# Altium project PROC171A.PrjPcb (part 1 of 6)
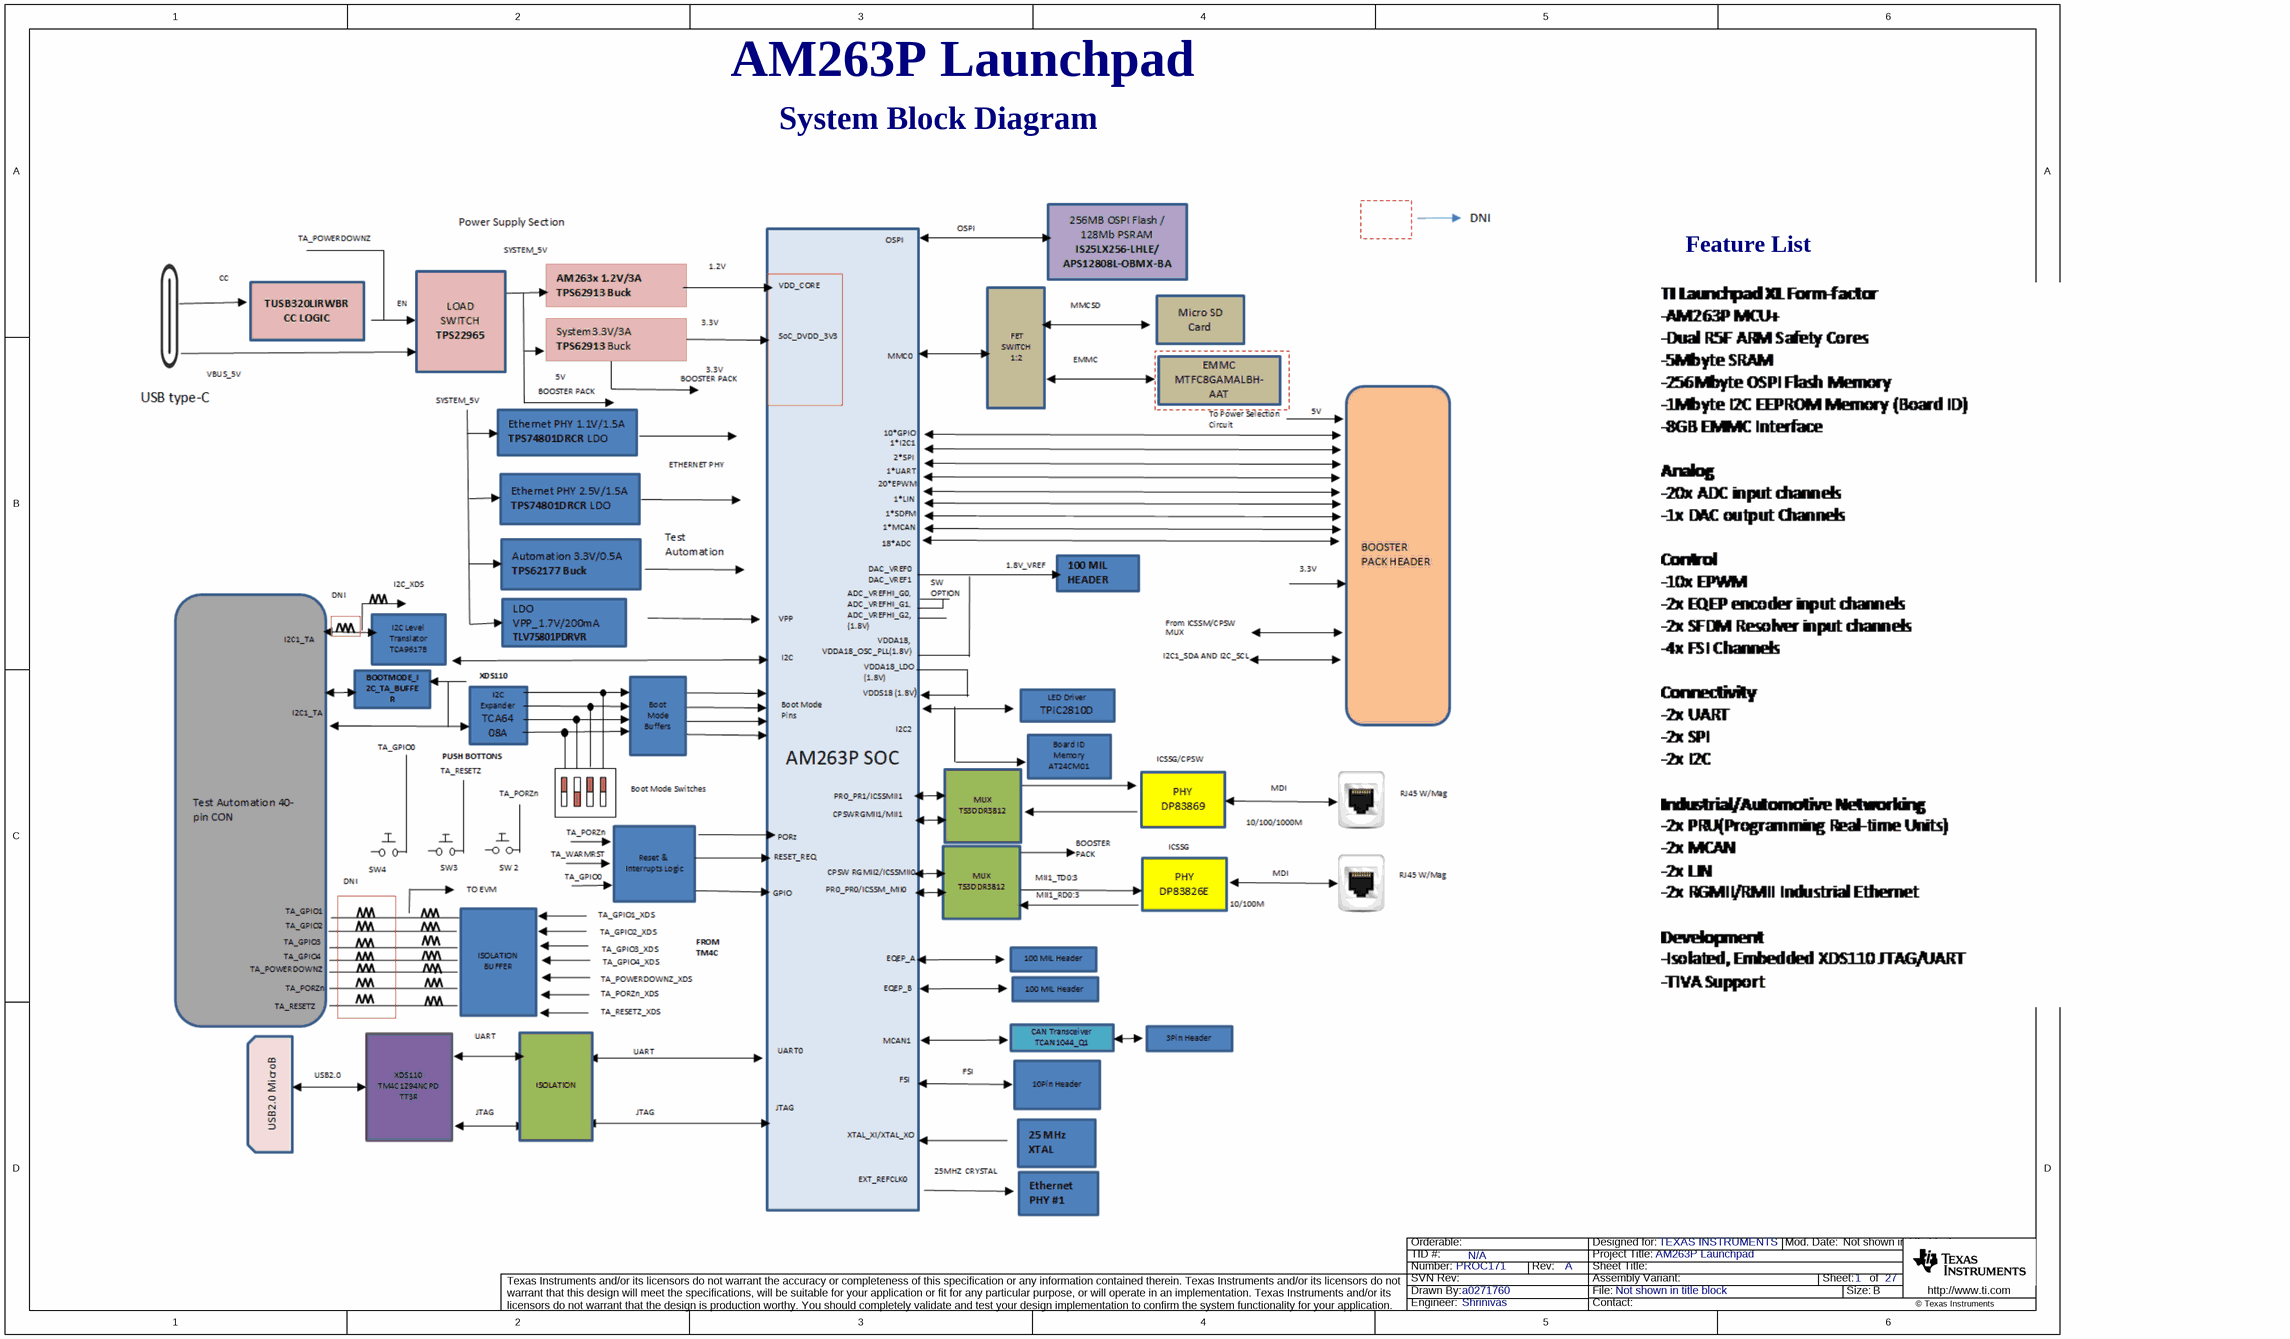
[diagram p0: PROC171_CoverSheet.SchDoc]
DrawnBy: a0271760; Layout Engineer: MISTRAL; PCB_Rev: A; PRJ_Customer: TEXAS INSTRUMENTS; PRJ_Engineer: Shrinivas; PRJ_Number: PROC171; PRJ_Title: AM263P Launchpad; Sch_Rev: A; TID: N/A
27 sheets, 919 parts. Net scope: global (net labels, ports and power ports of the same name join across sheets).
Sheets:
  PROC171_CoverSheet.SchDoc
  PROC171_Revision_History.SchDoc
  PROC171_System_Power_1.SchDoc
  PROC171_System_Power_2.SchDoc
  PROC171_AM263P_1_Power.SchDoc
  PROC171_AM263P_2_Clock_Reset_Boot_JTAG.SchDoc
  PROC171_AM263P_Serial_Connectivity.SchDoc
  PROC171_AM263P_3_OSPI_MMC.SchDoc
  PROC171_AM263P_4_EMMC.SchDoc
  PROC171_AM263P_5_ADC_DAC.SchDoc
  PROC171_AM263P_6_ePWM_eQEP_FSI.SchDoc
  PROC171_AM263P_7_RGMII_MII.SchDoc
  PROC171_AM263P_8_PRU.SchDoc
  PROC171_AM263P_9_SDFM.SchDoc
  PROC171_Push_Buttons.SchDoc
  PROC171_Test_Automation.SchDoc
  PROC171_Ehernet_PHY_1.SchDoc
  PROC171_Ehernet_PHY_2.SchDoc
  PROC171_Ehernet_RJ45_1.SchDoc
  PROC171_XDS110_2.SchDoc
  PROC171_Ehernet_RJ45_2.SchDoc
  PROC171_Boosterpack_Headers.SchDoc
  PROC171_Breakout_Headers.SchDoc
  PROC171_IO_EXPANDER.SchDoc
  PROC171_LED.SchDoc
  PROC171_XDS110_1.SchDoc
  PROC171_Hardware.SchDoc

## Sheet PROC171_CoverSheet.SchDoc
size 431 x 279 mm; Date: Not shown in title block; ApprovedBy: Not shown in title block; CheckedBy: Not shown in title block; Author: Not shown in title block; CompanyName: Not shown in title block; Engineer: Shrinivas/Rakesh; Organization: Not shown in title block; Address1: Not shown in title block; Address2: Not shown in title block; Address3: Not shown in title block; Address4: Not shown in title block; DocumentNumber: 1; Rev: A; SheetNumber: 1; SheetTotal: 27; PageSetup: Record=PageOptions¦CenterHorizontal=True¦CenterVertical=True¦PrintScale=1.00¦XCorrection=1.00¦YCorrection=1.00¦PrintKind=0¦BorderSize=5000000¦LeftOffset=0¦BottomOffset=0¦Orientation=2¦PaperLength=1000¦PaperWidth=1000¦Scale=100¦PaperSource=15¦PrintQuality=600¦MediaType=1¦DitherType=10¦PaperKind=Letter¦PrintScaleMode=1; Revision: E1

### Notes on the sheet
- AM263P Launchpad
- System Block Diagram
- Feature List

## Sheet PROC171_Revision_History.SchDoc
size 431 x 279 mm; Date: Not shown in title block; ApprovedBy: Not shown in title block; CheckedBy: Not shown in title block; Author: Not shown in title block; CompanyName: Not shown in title block; Engineer: Shrinivas/Rakesh; Organization: Not shown in title block; Address1: Not shown in title block; Address2: Not shown in title block; Address3: Not shown in title block; Address4: Not shown in title block; DocumentNumber: 2; Rev: A; SheetNumber: 2; SheetTotal: 27; PageSetup: Record=PageOptions¦CenterHorizontal=True¦CenterVertical=True¦PrintScale=1.00¦XCorrection=1.00¦YCorrection=1.00¦PrintKind=0¦BorderSize=5000000¦LeftOffset=0¦BottomOffset=0¦Orientation=2¦PaperLength=1000¦PaperWidth=1000¦Scale=100¦PaperSource=15¦PrintQuality=600¦MediaType=1¦DitherType=10¦PaperKind=Letter¦PrintScaleMode=1; Revision: E1
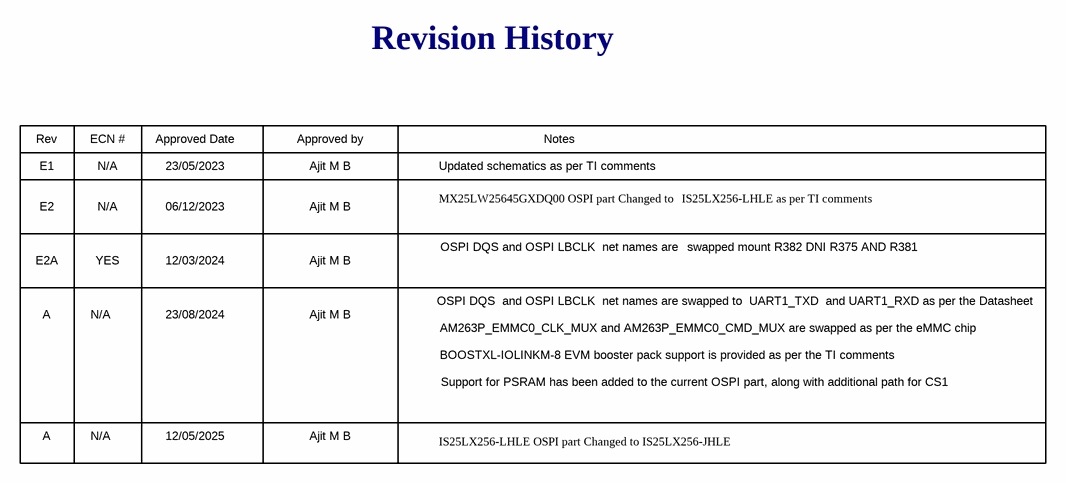
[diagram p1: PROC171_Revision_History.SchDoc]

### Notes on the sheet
- Revision History
- Rev
- ECN #
- Approved Date
- Approved by
- Notes
- E1
- E2
- N/A
- 23/05/2023
- 06/12/2023
- Ajit M B
- Updated schematics as per TI comments
- MX25LW25645GXDQ00 OSPI part Changed to
- IS25LX256-LHLE as per TI comments
- E2A
- YES
- 12/03/2024
- OSPI DQS and OSPI LBCLK  net names are
- swapped mount R382 DNI R375 AND R381
- A
- 23/08/2024
- BOOSTXL-IOLINKM-8 EVM booster pack support is provided as per the TI comments
- AM263P_EMMC0_CLK_MUX and AM263P_EMMC0_CMD_MUX are swapped as per the eMMC chip
- OSPI DQS  and OSPI LBCLK  net names are swapped to  UART1_TXD  and UART1_RXD as per the Datasheet
- Support for PSRAM has been added to the current OSPI part, along with additional path for CS1
- 12/05/2025
- IS25LX256-LHLE OSPI part Changed to IS25LX256-JHLE

## Sheet PROC171_System_Power_1.SchDoc
size 431 x 279 mm; Date: Not shown in title block; ApprovedBy: Not shown in title block; CheckedBy: Not shown in title block; Author: Not shown in title block; CompanyName: Not shown in title block; Engineer: Not shown in title block; Organization: Not shown in title block; Address1: Not shown in title block; Address2: Not shown in title block; Address3: Not shown in title block; Address4: Not shown in title block; DocumentNumber: 3; Revision: Use project parameter SCH_Rev; SheetNumber: 3; SheetTotal: 27; PageSetup: Record=PageOptions¦CenterHorizontal=True¦CenterVertical=True¦PrintScale=1.00¦XCorrection=1.00¦YCorrection=1.00¦PrintKind=0¦BorderSize=5000000¦LeftOffset=0¦BottomOffset=0¦Orientation=2¦PaperLength=1000¦PaperWidth=1000¦Scale=100¦PaperSource=15¦PrintQuality=600¦MediaType=1¦DitherType=10¦PaperKind=Letter¦PrintScaleMode=1
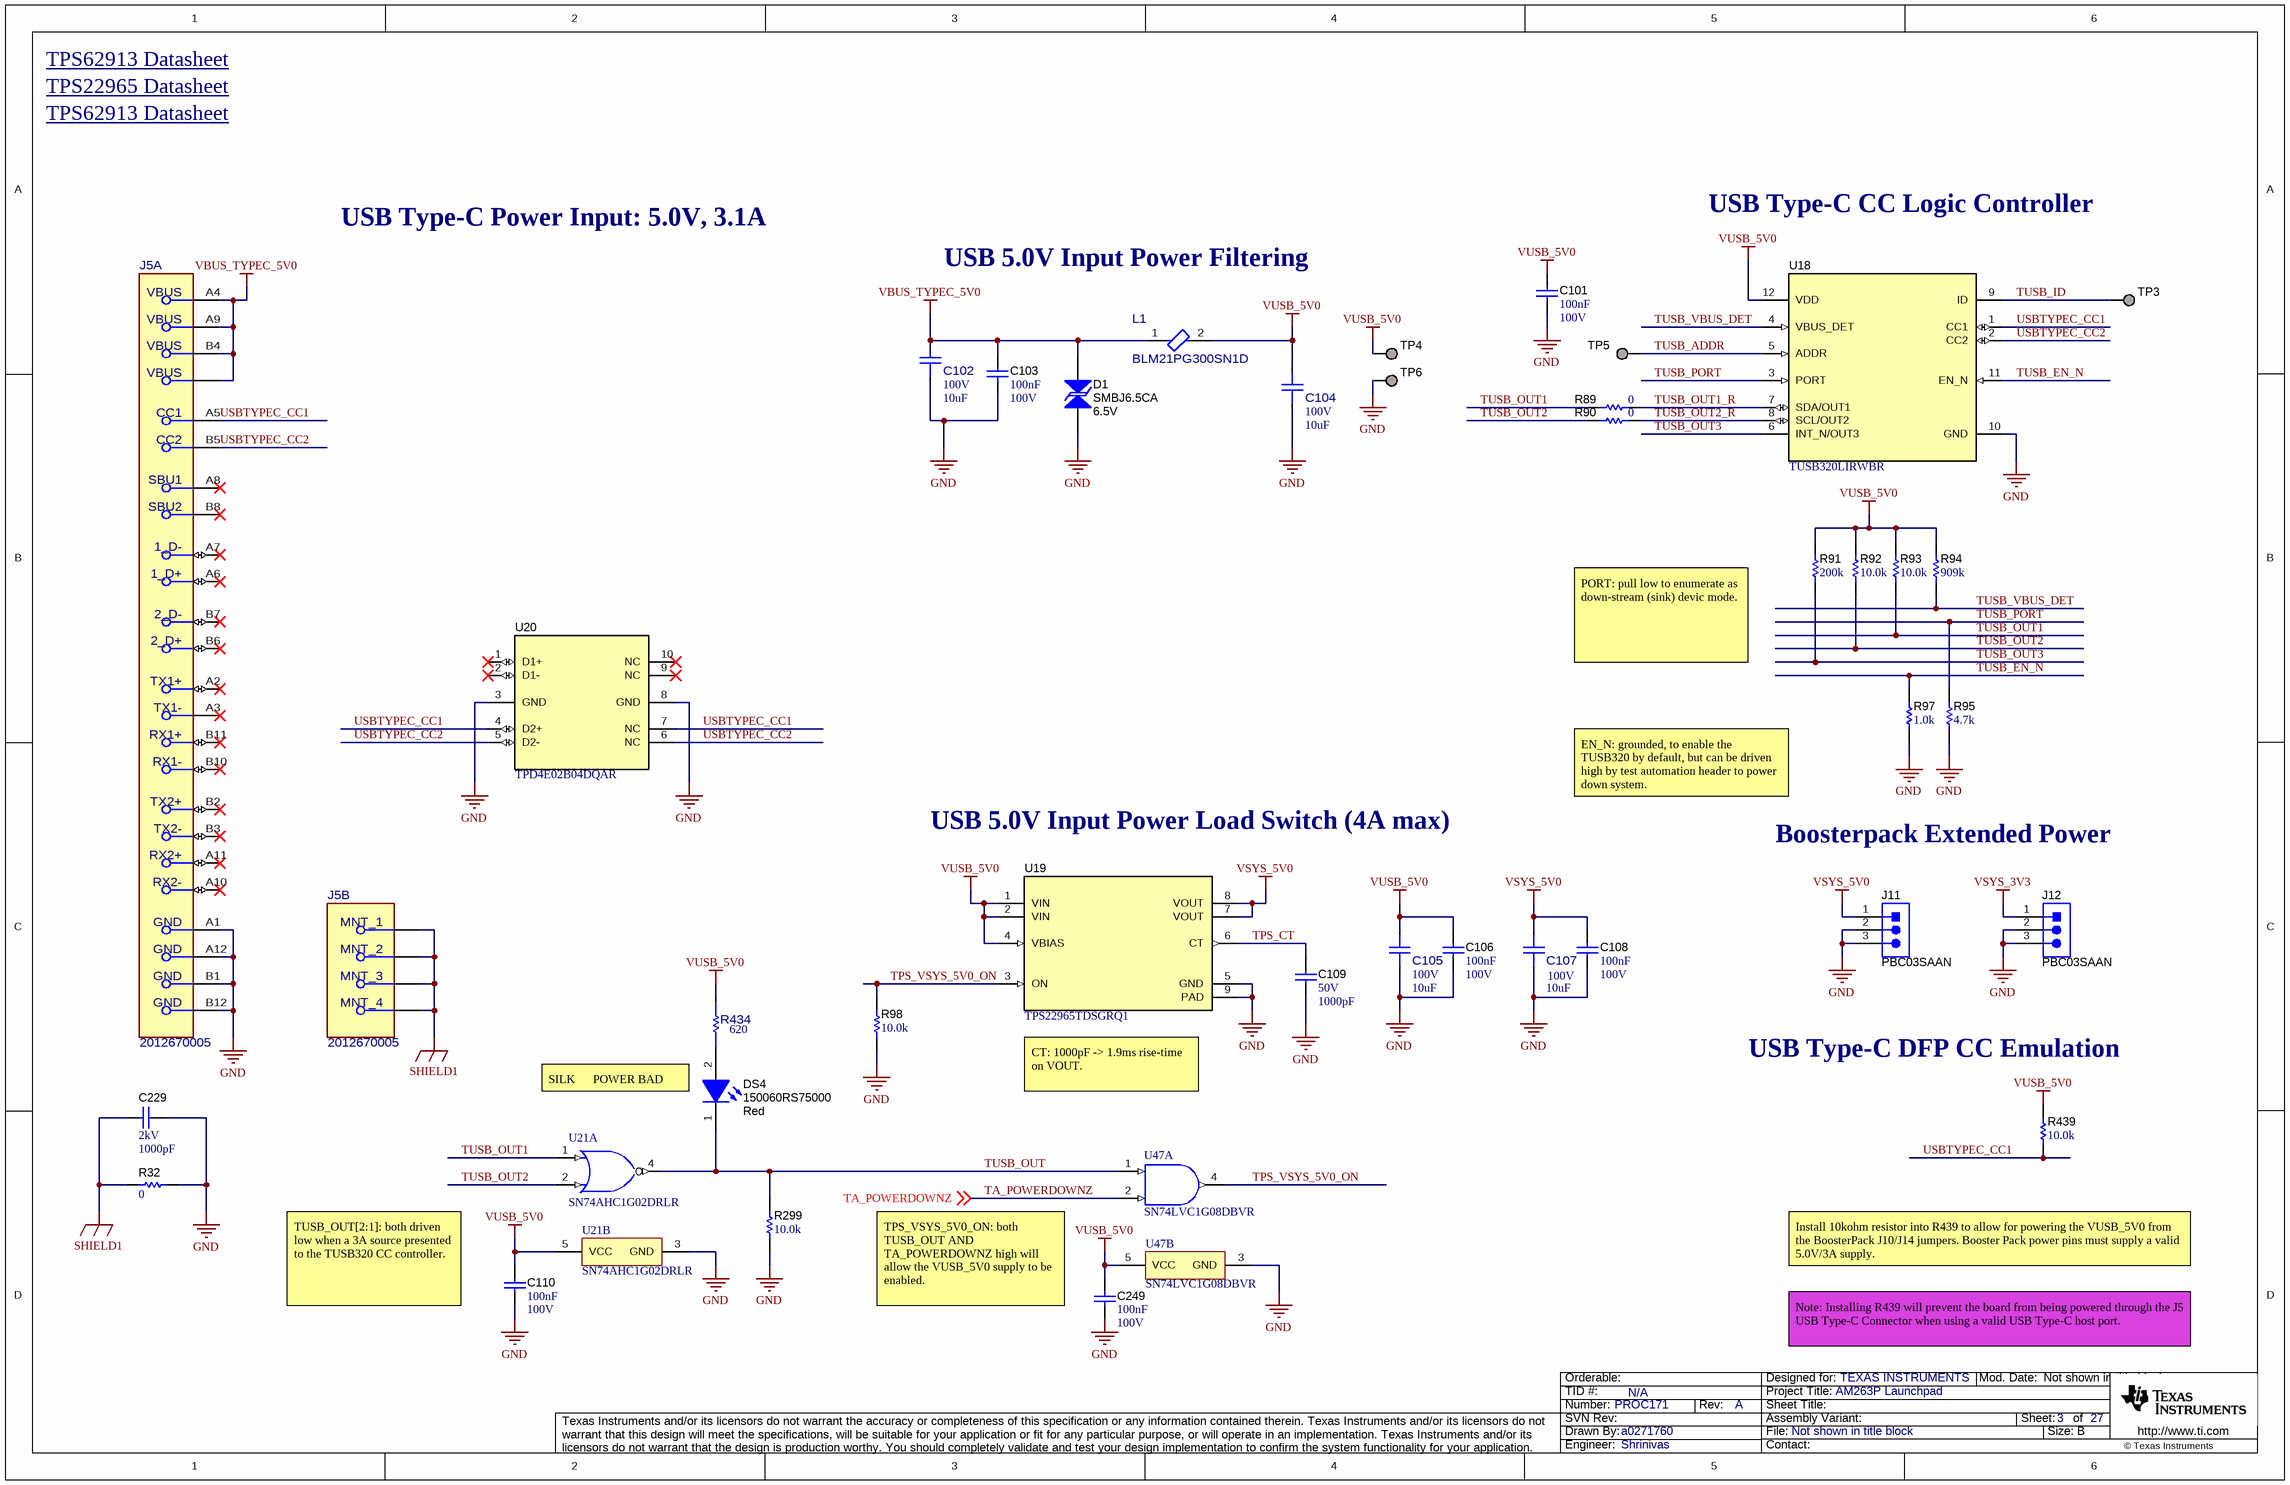
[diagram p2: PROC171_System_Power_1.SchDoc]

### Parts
C101  Cap_F: 100nF  VDC_V: 100V  [0603]  (hidden comment: GRM188R72A104KA35D)
C102  VDC_V: 100V  ValueDisplayed: 10uF  [FP-GRM32EC72A106KE05L_1210-MFG]  (hidden comment: GRM32EC72A106KE05L)
C103  Cap_F: 100nF  VDC_V: 100V  [0603]  (hidden comment: GRM188R72A104KA35J)
C104  VDC_V: 100V  ValueDisplayed: 10uF  [FP-GRM32EC72A106KE05L_1210-MFG]  (hidden comment: GRM32EC72A106KE05L)
C105  VDC_V: 100V  ValueDisplayed: 10uF  [FP-GRM32EC72A106KE05L_1210-MFG]  (hidden comment: GRM32EC72A106KE05L)
C106  Cap_F: 100nF  VDC_V: 100V  [0603]  (hidden comment: GRM188R72A104KA35D)
C107  VDC_V: 100V  ValueDisplayed: 10uF  [FP-GRM32EC72A106KE05L_1210-MFG]  (hidden comment: GRM32EC72A106KE05L)
C108  Cap_F: 100nF  VDC_V: 100V  [0603]  (hidden comment: GRM188R72A104KA35D)
C109  VDC_V: 50V  ValueDisplayed: 1000pF  [0402]  (hidden comment: GRM1555C1H102JA01D)
C110  Cap_F: 100nF  VDC_V: 100V  [0603]  (hidden comment: GRM188R72A104KA35D)
C229  VDC_V: 2kV  ValueDisplayed: 1000pF  [1808]  (hidden comment: GR442QR73D102KW01L)
C249  Cap_F: 100nF  VDC_V: 100V  [0603]  (hidden comment: GRM188R72A104KA35D)
D1  SMBJ6.5CA  value 6.5V  [SMB-Bi]
DS4  150060RS75000  value Red  [WL-SMCW_RED]
J5  2012670005  [FP-2012670005_CONN_USB_9MM39_8MM21-MFG]  (parts A,B of 2)
J11  PBC03SAAN  [PBC03SAAN]
J12  PBC03SAAN  [PBC03SAAN]
L1  BLM21PG300SN1D  [FP-BLM21PG300SN1D_0805-MFG]
R32  ValueDisplayed: 0  [0805_HV]  (hidden comment: ERJ-6GEY0R00V)
R89  ValueDisplayed: 0  [0402L]  (hidden comment: ERJ-2GE0R00X)
R90  ValueDisplayed: 0  [0402L]  (hidden comment: ERJ-2GE0R00X)
R91  ValueDisplayed: 200k  [0402]  (hidden comment: CRCW0402200KJNED)
R92  ValueDisplayed: 10.0k  [0402]  (hidden comment: ERJ-2RKF1002X)
R93  ValueDisplayed: 10.0k  [0402]  (hidden comment: ERJ-2RKF1002X)
R94  ValueDisplayed: 909k  [0402]  (hidden comment: CRCW0402909KFKED)
R95  ValueDisplayed: 4.7k  [0402]  (hidden comment: CRCW04024K70JNED)
R97  ValueDisplayed: 1.0k  [0402]  (hidden comment: ERJ-2GEJ102X)
R98  ValueDisplayed: 10.0k  [0402]  (hidden comment: ERJ-2RKF1002X)
R299  ValueDisplayed: 10.0k  [0402]  (hidden comment: ERJ-2RKF1002X)
R434  value 620  [FP-ERA-2APB621X_0402-MFG]  (hidden comment: ERA-2APB621X)
R439  ValueDisplayed: 10.0k  [0402]  (hidden comment: ERJ-2RKF1002X)
TP3  TESTPOINT  [TP_25MIL-SMT]  (value not drawn)  (no BOM)
TP4  TESTPOINT  [TP_25MIL-SMT]  (value not drawn)  (no BOM)
TP5  TESTPOINT  [TP_25MIL-SMT]  (value not drawn)  (no BOM)
TP6  TESTPOINT  [TP_25MIL-SMT]  (value not drawn)  (no BOM)
U18  TUSB320LIRWBR  [RWB0012A]
U19  TPS22965TDSGRQ1  [DSG0008B]
U20  TPD4E02B04DQAR  [DQA0010A]
U21  SN74AHC1G02DRLR  [DRL0005A]  (parts A,B of 2)
U47  SN74LVC1G08DBVR  [DBV0005A_N]  (parts A,B of 2)

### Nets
GND: C101.2 C102.1 C103.2 C104.1 C105.1 C106.2 C107.1 C108.2 C109.2 C110.2 C229.1 C249.2 D1.1 J5.A1(GND) J5.A12(GND) J5.B1(GND) J5.B12(GND) J11.2 J11.3 J12.2 J12.3 R32.2 R95.1 R97.1 R98.2 R299.2 TP6.1 U18.10(GND) U19.5(GND) U19.9(PAD) U20.3(GND) U20.8(GND) U21.3(GND) U47.3(GND)
SHIELD1: C229.2 J5.1(MNT_1) J5.2(MNT_2) J5.3(MNT_3) J5.4(MNT_4) R32.1
VBUS_TYPEC_5V0: C102.2 C103.1 D1.2 J5.A4(VBUS) J5.A9(VBUS) J5.B4(VBUS) J5.B9(VBUS) L1.1
VSYS_3V3: J12.1
VSYS_5V0: C107.2 C108.1 J11.1 U19.7(VOUT) U19.8(VOUT)
VUSB_5V0: C101.1 C104.2 C105.2 C106.1 C110.1 C249.1 L1.2 R91.2 R92.1 R93.1 R94.2 R434.2 R439.1 TP4.1 U18.12(VDD) U19.1(VIN) U19.2(VIN) U19.4(VBIAS) U21.5(VCC) U47.5(VCC)
TA_POWERDOWNZ: U47.2(B) ; off-sheet TA_POWERDOWNZ
TPS_CT: C109.1 U19.6(CT)
TPS_VSYS_5V0_ON: R98.1 U19.3(ON) U47.4(Y)
TUSB_ADDR: TP5.1 U18.5(ADDR)
TUSB_EN_N: R97.2 U18.11(EN_N)
TUSB_ID: TP3.1 U18.9(ID)
TUSB_OUT: DS4.1(K) R299.1 U21.4(Y) U47.1(A)
TUSB_OUT1: R89.2 R93.2 U21.1(A)
TUSB_OUT1_R: R89.1 U18.7(SDA/OUT1)
TUSB_OUT2: R90.2 R92.2 U21.2(B)
TUSB_OUT2_R: R90.1 U18.8(SCL/OUT2)
TUSB_OUT3: R91.1 U18.6(INT_N/OUT3)
TUSB_PORT: R95.2 U18.3(PORT)
TUSB_VBUS_DET: R94.1 U18.4(VBUS_DET)
USBTYPEC_CC1: J5.A5(CC1) R439.2 U18.1(CC1) U20.4(D2+) U20.7(NC)
USBTYPEC_CC2: J5.B5(CC2) U18.2(CC2) U20.5(D2-) U20.6(NC)
NetDS4_2: DS4.2(A) R434.1

Not connected (* = marked no-connect by the designer): J5 A2(TX1+)* A3(TX1-)* A6(1_D+)* A7(1_D-)* A8(SBU1)* A10(RX2-)* A11(RX2+)* B2(TX2+)* B3(TX2-)* B6(2_D+)* B7(2_D-)* B8(SBU2)* B10(RX1-)* B11(RX1+)*; U20 1(D1+)* 2(D1-)* 9(NC)* 10(NC)*

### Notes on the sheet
- TPS62913 Datasheet <https://www.ti.com/product/TPS62913>
- TPS22965 Datasheet <http://www.ti.com/lit/ds/symlink/tps22965-q1.pdf>
- TPS62913 Datasheet <datasheets/IC-TPS62913RPUR.pdf>
- USB Type-C Power Input: 5.0V, 3.1A
- USB Type-C CC Logic Controller
- USB 5.0V Input Power Filtering
- PORT: pull low to enumerate as down-stream (sink) devic mode.
- USB 5.0V Input Power Load Switch (4A max)
- EN_N: grounded, to enable the TUSB320 by default, but can be driven high by test automation header to power down system.
  TA_POWERDOWNZ: pulled high by default. Can be driven low by TA Header to disable USB 5.0V supply.
- Boosterpack Extended Power
- SILK      POWER BAD
- (near U19) CT: 1000pF -> 1.9ms rise-time on VOUT.
- USB Type-C DFP CC Emulation
- TUSB_OUT[2:1]: both driven low when a 3A source presented to the TUSB320 CC controller.
- (near C249) TPS_VSYS_5V0_ON: both TUSB_OUT AND TA_POWERDOWNZ high will allow the VUSB_5V0 supply to be enabled.
- Install 10kohm resistor into R439 to allow for powering the VUSB_5V0 from the BoosterPack J10/J14 jumpers. Booster Pack power pins must supply a valid 5.0V/3A supply.
- Note: Installing R439 will prevent the board from being powered through the J5 USB Type-C Connector when using a valid USB Type-C host port.

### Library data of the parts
C101 C106 C108 C110 C249 = CMP-0007469-4: CAP, CERM, 0.1 uF, 100 V, +/- 10%, X7R, 0603; Manufacturer: MuRata; TaMin_C: -55°C; Polarized: N; SizeAreaWB_mm2: 4.68; Value1: Unknown; U/M: EA; Value: 0.1uF; TaMax_C: 125°C; SizeZ_mm: 1; SizeX_mm: 1.6; SizeY_mm: 0.8; SizeArea_mm2: 1.28; AEC Category: Q200
C102 C104 C105 C107 = CMP-0087970-1: 10µF ±10% 100V Ceramic Capacitor X7S 1210 (3225 Metric); Manufacturer: Murata; TempCo: 22%; SizeZ_mm: 2.7mm; AEC Qualified: No; Symbol Name: SYM-GRM32EC72A106KE05L
C103 = CMP-0007470-5: CAP, CERM, 0.1 uF, 100 V, +/- 10%, X7R, 0603; Manufacturer: MuRata; TaMin_C: -55°C; Polarized: N; SizeAreaWB_mm2: 4.68; Value1: Unknown; U/M: EA; Value: 0.1uF; TaMax_C: 125°C; SizeZ_mm: 1; SizeX_mm: 1.6; SizeY_mm: 0.8; SizeArea_mm2: 1.28; AEC Category: Q200
C109 = CMP-0006412-2: CAP, CERM, 1000 pF, 50 V, +/- 5%, C0G/NP0, 0402; Manufacturer: MuRata; TaMin_C: -55°C; Polarized: N; SizeAreaWB_mm2: 3; Value1: Unknown; U/M: EA; Value: 1000pF; TaMax_C: 125°C; SizeZ_mm: 0.6; SizeX_mm: 1; SizeY_mm: 0.5; Cap_F: 1nF; AEC Category: Q200
C229 = CMP-0009436-2: CAP, CERM, 1000 pF, 2000 V, +/- 10%, X7R, 1808; Manufacturer: MuRata; TaMin_C: -55°C; Polarized: N; SizeAreaWB_mm2: 16.5; Value1: Unknown; U/M: EA; Value: 1000pF; TaMax_C: 125°C; SizeZ_mm: 2.03; SizeX_mm: 4.5; SizeY_mm: 2; Value2: 2000V; SizeArea_mm2: 9; Cap_F: 1nF; AEC Category: Q200
D1 = CMP-0005599-2: Diode, TVS, Bi, 6.5 V, SMB; Manufacturer: Littelfuse; SizeZ_mm: 2.6; SizeY_mm: 3.81; Ppk: 600W; AEC Category: Q101; RJA_CperW: 100; SizeArea_mm2: 21.336; SizeX_mm: 5.6; SizeAreaWB_mm2: 44.156
DS4 = CMP-0002947-3: LED, Red, SMD; Manufacturer: Wurth Elektronik; Value1: 0.072W; Vf_V: 2V; Angle: 140; Tjmax_C: 85°C; Type: AlInGaP; Vr_V: 5V; Io_A: 30mA; Power_TotalModule: 72mW
J5 = CMP-0093552-1: USB-C (USB TYPE-C) USB 3.2 Gen 2 (USB 3.1 Gen 2, Superspeed + (USB 3.1)) Receptacle Connector 24 Position Surface Mount, Right Angle; Through Hole; Manufacturer: Molex; Voltage_V: 30V; SizeZ_mm: 3.86mm; DUT-Pitch_mm: 0.5mm; Shrouded: true; ContactFinish: Gold,Nickel; Usb Standard: USB 3.1; AEC Qualified: No; Is Female: yes
J11 J12 = CMP-0002334-1: Header, 100mil, 3x1, Gold, TH; Manufacturer: Sullins Connector Solutions; CNHeader: TRUE; Green_Lifecycle: Not Set; Green_REACh: Incomplete; CT: FALSE
L1 = CMP-0098084-1: Chip Ferrite Bead, 0805, 30Ω @ 100MHz, 0.014Ω, , 4A; Manufacturer: Murata; DCR_ohm: 14m; SizeZ_mm: 1.05mm; Ciiva Ids: 886678; Import Ts: 1521843479; AEC Qualified: No
R32 = CMP-0020616-3: RES, 0, 5%, 0.125 W, AEC-Q200 Grade 0, 0805; Manufacturer: Panasonic; Power_W: 125mW; TempCo: 600 ppm/C; Value_Code: 0000; Value: 0; EIA_Code: E24; SizeX_mm: 2; SizeY_mm: 1.25; SizeZ_mm: 1.45; Value2: 0.125W; SizeArea_mm2: 2.5; AEC Qualified: Y; VDC_V: 150V; AEC Category: Q200; SizeAreaWB_mm2: 6.75
R89 R90 = CMP-0026992-3: RES, 0, 5%, 0.1 W, AEC-Q200 Grade 0, 0402; Manufacturer: Panasonic; Power_W: 100mW; TempCo: 600 ppm/C; Value_Code: 0000; Value: 0; EIA_Code: E24; SizeX_mm: 1; SizeY_mm: 0.5; SizeZ_mm: 0.6; Value2: 0.1W; AEC Qualified: Y; VDC_V: 50V; AEC Category: Q200; SizeAreaWB_mm2: 3
R91 = CMP-0026873-2: RES, 200 k, 5%, 0.063 W, AEC-Q200 Grade 0, 0402; Manufacturer: Vishay-Dale; Power_W: 63mW; TempCo: 200 ppm/C; Value: 200k; EIA_Code: E24; SizeX_mm: 1; SizeY_mm: 0.5; SizeZ_mm: 0.6; Value2: 0.063W; AEC Qualified: Y; VDC_V: 50V; AEC Category: Q200; AEC Grade: 0
R92 R93 R98 R299 R439 = CMP-0026658-1: RES, 10.0 k, 1%, 0.1 W, 0402; Manufacturer: Panasonic; Power_W: 100mW; TempCo: 100 ppm/C; Value_Code: 10k0; U/M: EA; Value: 10.0k; EIA_Code: E96; Res_ohm: 10k; SizeX_mm: 1; SizeY_mm: 0.5; SizeZ_mm: 0.6; Value2: 0.1W; VDC_V: 50V; AEC Category: Q200
R94 = CMP-0026603-2: RES, 909 k, 1%, 0.063 W, AEC-Q200 Grade 0, 0402; Manufacturer: Vishay-Dale; Power_W: 63mW; TempCo: 100 ppm/C; Value: 909k; EIA_Code: E96; SizeX_mm: 1; SizeY_mm: 0.5; SizeZ_mm: 0.6; Value2: 0.063W; AEC Qualified: Y; VDC_V: 50V; AEC Category: Q200; AEC Grade: 0
R95 = CMP-0026938-5: RES, 4.7 k, 5%, 0.063 W, AEC-Q200 Grade 0, 0402; Manufacturer: Vishay-Dale; Power_W: 63mW; TempCo: 200 ppm/C; Value_Code: 4k70; Value: 4.7k; EIA_Code: E24; SizeX_mm: 1; SizeY_mm: 0.5; SizeZ_mm: 0.6; Value2: 0.063W; AEC Qualified: Y; VDC_V: 50V; AEC Category: Q200; AEC Grade: 0
R97 = CMP-0078193-1: RES, 1.0 k, 5%, 0.1 W, AEC-Q200 Grade 0, 0402; Manufacturer: Panasonic; Value_Code: 1k00; SizeArea_mm2: 0.5; AEC Qualified: Y; AEC Category: Q200; Res_ohm: 1k; Value: 1.0k; SizeZ_mm: 0.6; Green_REACh: Passed; EIA_Code: E24; TempCo: 200 ppm/C; AEC Grade: 0; Power_W: 100mW; VDC_V: 50V; Value2: 0.1W; Green_Lifecycle: Active; U/M: EA; SizeX_mm: 1
R434 = CMP-0093717-1: 620 Ohms ±0.1% 0.063W, 1/16W Chip Resistor 0402 (1005 Metric) Automotive AEC-Q200 Thin Film; Manufacturer: Panasonic; VDC_V: 50V; AEC Grade: Grade 0; TempCo: 15ppm/°C; AEC Qualified: Yes; SizeZ_mm: 0.4mm; Power_W: 63mW
TP3-TP6 = CMP-0078143-3: TEST POINT.  No entry in BOM.
U18 = CMP-0073635-2: USB Type-C Configuration Channel Logic and Port Control, RWB0012A (X2QFN-12); Alternate Manufacturer: Texas Instruments; SizeAreaWB_mm2: 6.76; SizeZ_mm: 0.4; SizeX_mm: 1.6; SizeArea_mm2: 2.56; CompType: IC; AEC Category: Q200; AEC Qualified: N; Rating: Catalog
U19 = CMP-0073678-3: 5.5V, 4A, 16mΩ Automotive Load Switch With Adjustable Rise Time and Optional Quick Output Discharge, DSG0008B (WSON-8); Alternate PartNumber: TPS22965TDSGTQ1; Alternate Manufacturer: Texas Instruments; Green_Lifecycle: Active; SizeAreaWB_mm2: 9.0; Green_REACh: Passed; U/M: EA; SizeZ_mm: 0.8; SizeX_mm: 2.0; SizeArea_mm2: 4.0; CompType: IC; AEC Category: Q200; AEC Qualified: Y
U20 = CMP-0073612-3: 4-Channel ESD Protection Diode for USB Type-C and HDMI 2.0, DQA0010A (USON-10); Alternate Manufacturer: Texas Instruments; Green_Lifecycle: Active; SizeAreaWB_mm2: 7.0; Green_REACh: Passed; SizeZ_mm: 0.55; SizeX_mm: 1.0; SizeY_mm: 2.5; CompType: IC; AEC Category: Q200; AEC Qualified: Y
U21 = CMP-0051530-2: Single 2-Input Positive-NOR Gate, DRL0005A, LARGE T&R; Manufacturer: Texas Instruments; Schmitt Trigger: No; Technology Family: AHC; Logic: True; Gate Type: NOR; Output Type: CMOS; Sub-Family: NAND Gate; Rating: Catalog; F @ Nom Voltage(Max)(Mhz): 75; ICC @ Nom Voltage(Max)(mA): 0.01; tpd @ Nom Voltage(Max)(ns): 11.4,7.5; Voltage(Nom)(V): 3.3,5; Output Drive (IOL/IOH)(Max)(mA): 50/-50; VCC(Max)(V): 5.5; VCC(Min)(V): 2; Bits(#): 1; AEC Category: Q200; AEC Qualified: N; CompType: IC; SizeArea_mm2: 2.56; SizeX_mm: 1.6; SizeZ_mm: 0.6
U47 = CMP-0051588-2: Single 2-Input Positive-AND Gate, DBV0005A, LARGE T&R; Manufacturer: Texas Instruments; Logic: True; ICC @ Nom Voltage(Max)(mA): 0.01; VCC(Min)(V): 1.65; Bits(#): 1; Rating: Catalog; Schmitt Trigger: No; Voltage(Nom)(V): 1.8,2.5,3.3,5; Output Drive (IOL/IOH)(Max)(mA): 32/-32; Gate Type: AND; tpd @ Nom Voltage(Max)(ns): 4.5,6,4,5; VCC(Max)(V): 5.5; Output Type: CMOS; F @ Nom Voltage(Max)(Mhz): 150; Input Type: CMOS/TTL; Technology Family: LVC; AEC Category: Q200; AEC Qualified: N; CompType: IC

## Sheet PROC171_System_Power_2.SchDoc
size 431 x 279 mm; Date: Not shown in title block; ApprovedBy: Not shown in title block; CheckedBy: Not shown in title block; Author: Not shown in title block; CompanyName: Not shown in title block; Engineer: Not shown in title block; Organization: Not shown in title block; Address1: Not shown in title block; Address2: Not shown in title block; Address3: Not shown in title block; Address4: Not shown in title block; DocumentNumber: 4; Revision: Use project parameter SCH_Rev; SheetNumber: 4; SheetTotal: 27; PageSetup: Record=PageOptions¦CenterHorizontal=True¦CenterVertical=True¦PrintScale=1.00¦XCorrection=1.00¦YCorrection=1.00¦PrintKind=0¦BorderSize=5000000¦LeftOffset=0¦BottomOffset=0¦Orientation=2¦PaperLength=1000¦PaperWidth=1000¦Scale=100¦PaperSource=15¦PrintQuality=600¦MediaType=1¦DitherType=10¦PaperKind=Letter¦PrintScaleMode=1
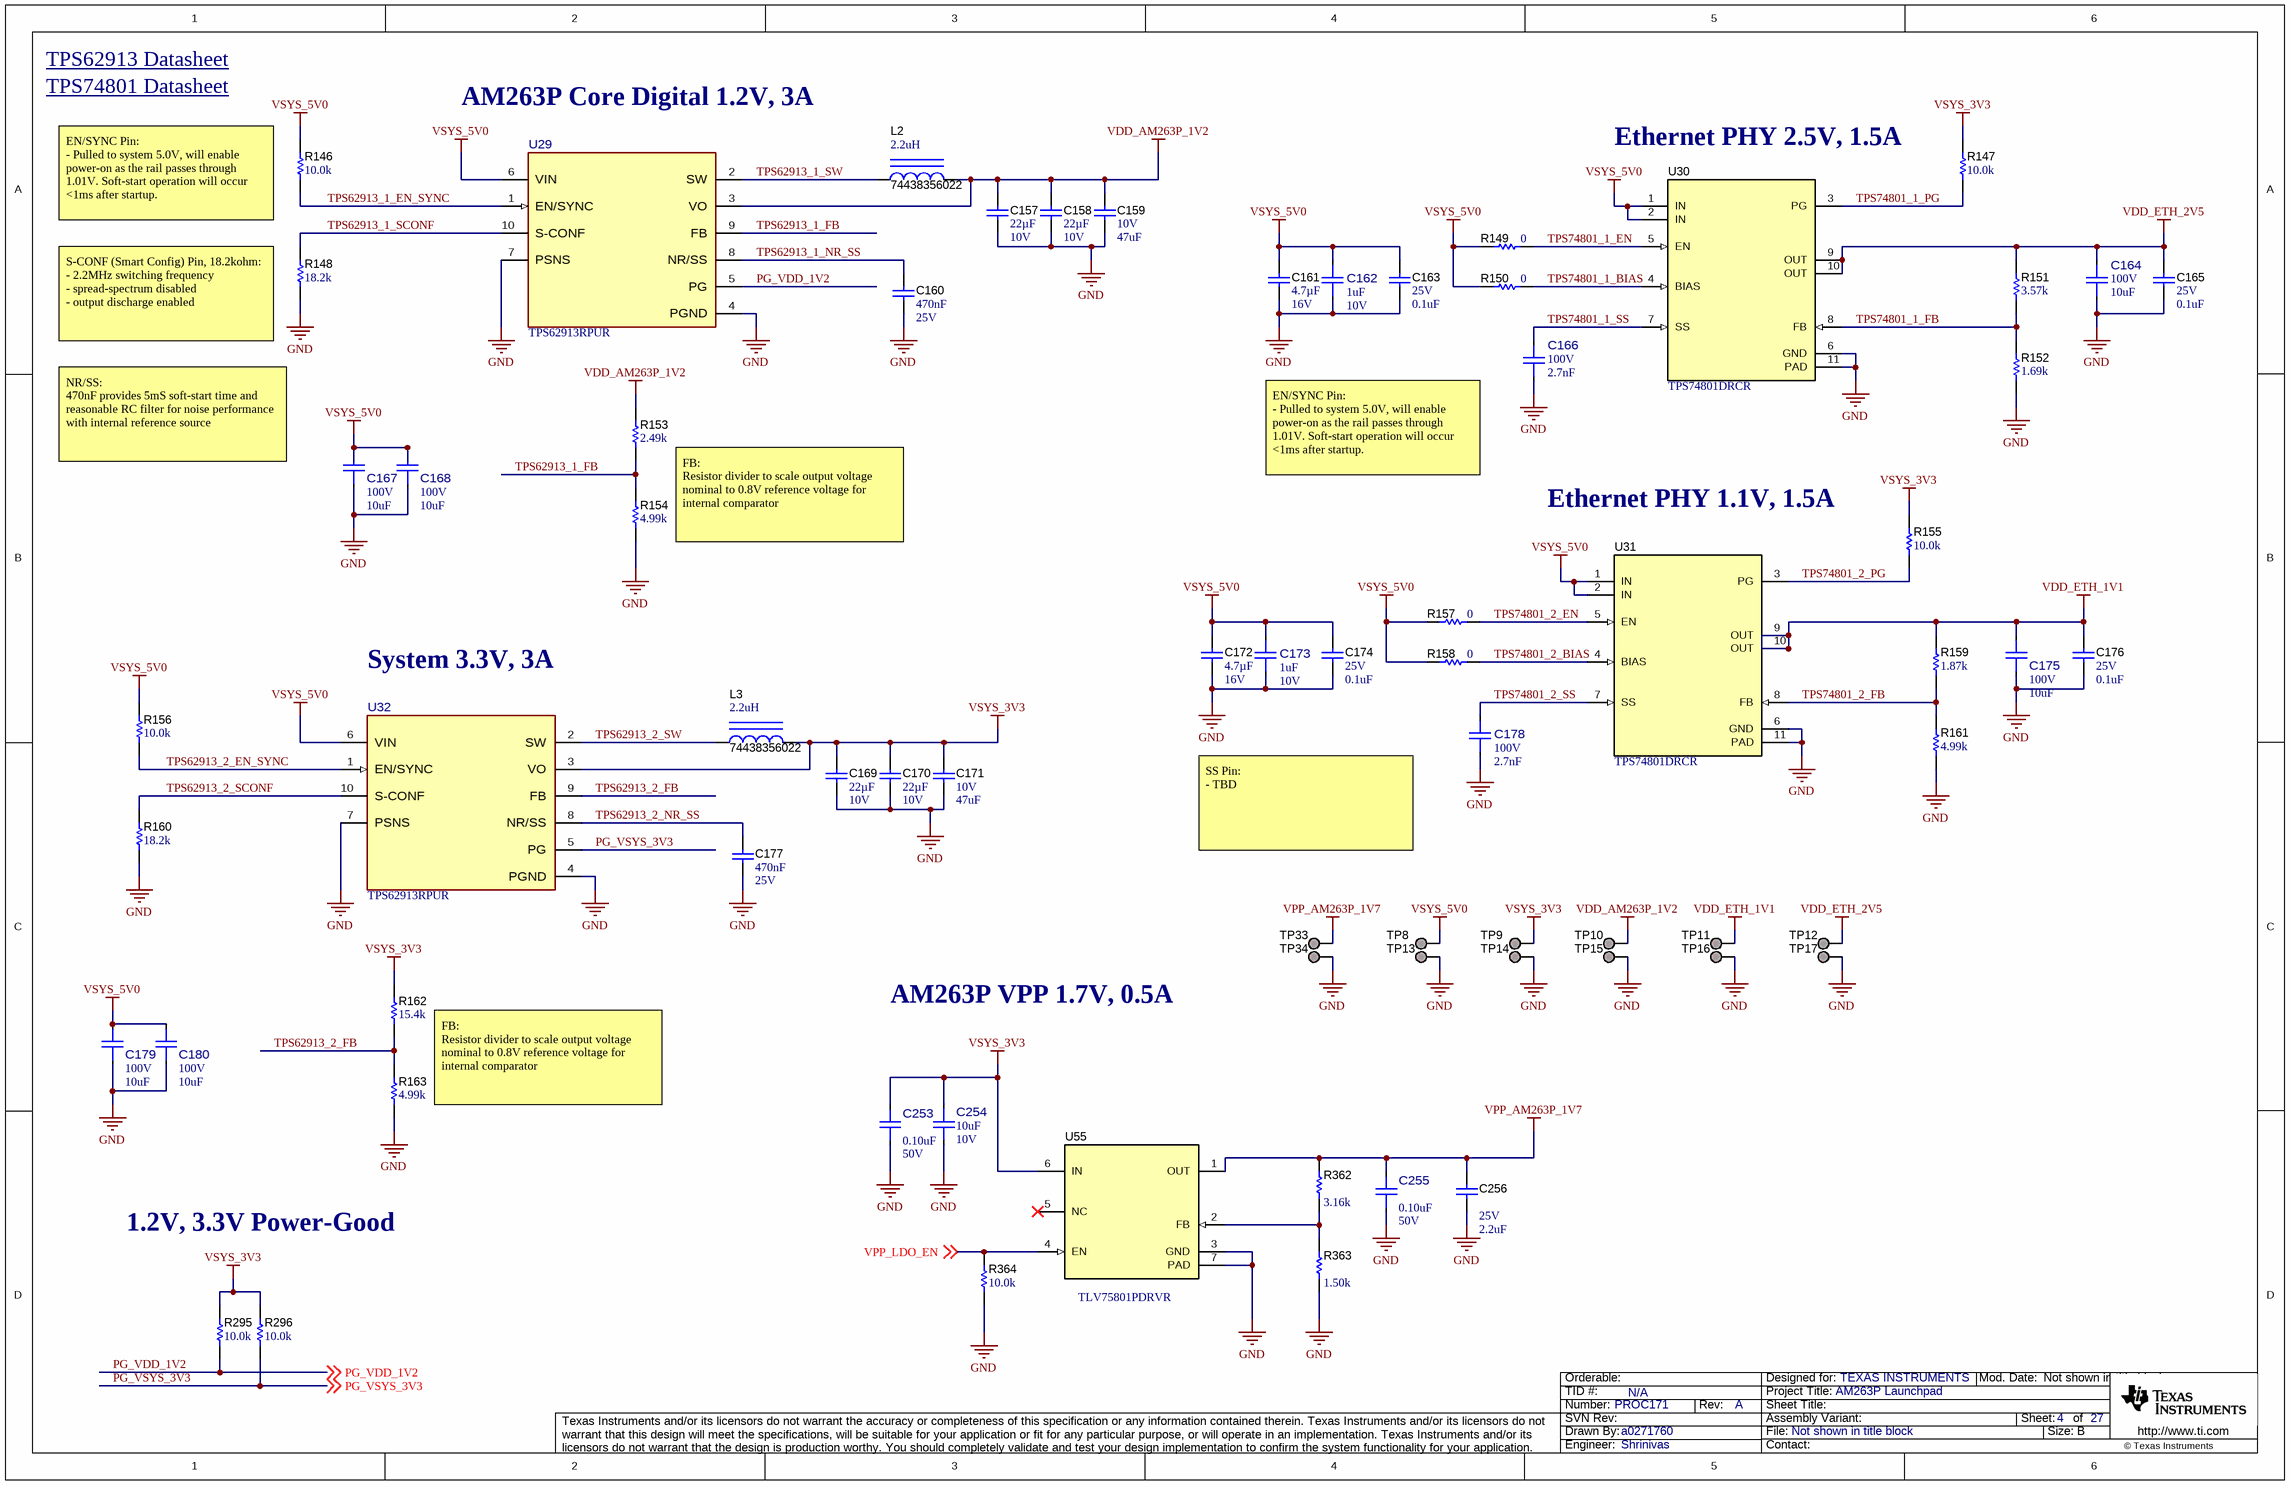
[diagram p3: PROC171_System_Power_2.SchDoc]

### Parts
C157  Cap_F: 22µF  VDC_V: 10V  [0805_HV]  (hidden comment: GRM21BZ71A226ME15L)
C158  Cap_F: 22µF  VDC_V: 10V  [0805_HV]  (hidden comment: GRM21BZ71A226ME15L)
C159  VDC_V: 10V  ValueDisplayed: 47uF  [1210_270]  (hidden comment: GRM32ER71A476ME15L)
C160  Cap_F: 470nF  VDC_V: 25V  [0603]  (hidden comment: GRM188R71E474KA12D)
C161  Cap_F: 4.7µF  VDC_V: 16V  [0603]  (hidden comment: GRM188Z71C475KE21D)
C162  ValueDisplayed: 1uF  VDC_V: 10V  [FP-GRM155C71A105KE11D_0402-MFG]  (hidden comment: GRM155C71A105KE11D)
C163  VDC_V: 25V  ValueDisplayed: 0.1uF  [0402]  (hidden comment: GRM155R71E104KE14D)
C164  VDC_V: 100V  ValueDisplayed: 10uF  [FP-GRM32EC72A106KE05L_1210-MFG]  (hidden comment: GRM32EC72A106KE05L)
C165  VDC_V: 25V  ValueDisplayed: 0.1uF  [0402]  (hidden comment: GRM155R71E104KE14D)
C166  VDC_V: 100V  ValueDisplayed: 2.7nF  [FP-GCM155R72A272KA37D_0402-MFG]  (hidden comment: GCM155R72A272KA37D)
C167  VDC_V: 100V  ValueDisplayed: 10uF  [FP-GRM32EC72A106KE05L_1210-MFG]  (hidden comment: GRM32EC72A106KE05L)
C168  VDC_V: 100V  ValueDisplayed: 10uF  [FP-GRM32EC72A106KE05L_1210-MFG]  (hidden comment: GRM32EC72A106KE05L)
C169  Cap_F: 22µF  VDC_V: 10V  [0805_HV]  (hidden comment: GRM21BZ71A226ME15L)
C170  Cap_F: 22µF  VDC_V: 10V  [0805_HV]  (hidden comment: GRM21BZ71A226ME15L)
C171  VDC_V: 10V  ValueDisplayed: 47uF  [1210_270]  (hidden comment: GRM32ER71A476ME15L)
C172  Cap_F: 4.7µF  VDC_V: 16V  [0603]  (hidden comment: GRM188Z71C475KE21D)
C173  ValueDisplayed: 1uF  VDC_V: 10V  [FP-GRM155C71A105KE11D_0402-MFG]  (hidden comment: GRM155C71A105KE11D)
C174  VDC_V: 25V  ValueDisplayed: 0.1uF  [0402]  (hidden comment: GRM155R71E104KE14D)
C175  VDC_V: 100V  ValueDisplayed: 10uF  [FP-GRM32EC72A106KE05L_1210-MFG]  (hidden comment: GRM32EC72A106KE05L)
C176  VDC_V: 25V  ValueDisplayed: 0.1uF  [0402]  (hidden comment: GRM155R71E104KE14D)
C177  Cap_F: 470nF  VDC_V: 25V  [0603]  (hidden comment: GRM188R71E474KA12D)
C178  VDC_V: 100V  ValueDisplayed: 2.7nF  [FP-GCM155R72A272KA37D_0402-MFG]  (hidden comment: GCM155R72A272KA37D)
C179  VDC_V: 100V  ValueDisplayed: 10uF  [FP-GRM32EC72A106KE05L_1210-MFG]  (hidden comment: GRM32EC72A106KE05L)
C180  VDC_V: 100V  ValueDisplayed: 10uF  [FP-GRM32EC72A106KE05L_1210-MFG]  (hidden comment: GRM32EC72A106KE05L)
C253  ValueDisplayed: 0.10uF  VDC_V: 50V  [FP-GRM155R71H104KE14D_0402-MFG]  (hidden comment: GRM155R71H104KE14D)
C254  ValueDisplayed: 10uF  VDC_V: 10V  [FP-KGM05CR51A106MH_0402-MFG]  (hidden comment: KGM05CR51A106MH)
C255  ValueDisplayed: 0.10uF  VDC_V: 50V  [FP-GRM155R71H104KE14D_0402-MFG]  (hidden comment: GRM155R71H104KE14D)
C256  VDC_V: 25V  ValueDisplayed: 2.2uF  [0402_070]  (hidden comment: GRM155R61E225KE11D)
L2  74438356022  ValueDisplayed: 2.2uH  [WE-MAPI_4020]
L3  74438356022  ValueDisplayed: 2.2uH  [WE-MAPI_4020]
R146  ValueDisplayed: 10.0k  [0402]  (hidden comment: ERJ-2RKF1002X)
R147  ValueDisplayed: 10.0k  [0402]  (hidden comment: ERJ-2RKF1002X)
R148  ValueDisplayed: 18.2k  [0805_HV]  (hidden comment: ERJ-6ENF1822V)
R149  ValueDisplayed: 0  [0402]  (hidden comment: ERJ-2GE0R00X)
R150  ValueDisplayed: 0  [0402]  (hidden comment: ERJ-2GE0R00X)
R151  ValueDisplayed: 3.57k  [0402]  (hidden comment: CRCW04023K57FKED)
R152  ValueDisplayed: 1.69k  [0402]  (hidden comment: CRCW04021K69FKED)
R153  ValueDisplayed: 2.49k  [0402]  (hidden comment: CRCW04022K49FKED)
R154  ValueDisplayed: 4.99k  [0402]  (hidden comment: CRCW04024K99FKED)
R155  ValueDisplayed: 10.0k  [0402]  (hidden comment: ERJ-2RKF1002X)
R156  ValueDisplayed: 10.0k  [0402]  (hidden comment: ERJ-2RKF1002X)
R157  ValueDisplayed: 0  [0402]  (hidden comment: ERJ-2GE0R00X)
R158  ValueDisplayed: 0  [0402]  (hidden comment: ERJ-2GE0R00X)
R159  ValueDisplayed: 1.87k  [0402]  (hidden comment: CRCW04021K87FKED)
R160  ValueDisplayed: 18.2k  [0805_HV]  (hidden comment: ERJ-6ENF1822V)
R161  ValueDisplayed: 4.99k  [0402]  (hidden comment: CRCW04024K99FKED)
R162  ValueDisplayed: 15.4k  [0402]  (hidden comment: CRCW040215K4FKED)
R163  ValueDisplayed: 4.99k  [0402]  (hidden comment: CRCW04024K99FKED)
R295  ValueDisplayed: 10.0k  [0402]  (hidden comment: ERJ-2RKF1002X)
R296  ValueDisplayed: 10.0k  [0402]  (hidden comment: ERJ-2RKF1002X)
R362  ValueDisplayed: 3.16k  [0603]  (hidden comment: RC0603FR-073K16L)
R363  ValueDisplayed: 1.50k  [0402]  (hidden comment: CRCW04021K50FKED)
R364  ValueDisplayed: 10.0k  [0402]  (hidden comment: ERJ-2RKF1002X)
TP8  TESTPOINT  [TP_25MIL-SMT]  (value not drawn)  (no BOM)
TP9  TESTPOINT  [TP_25MIL-SMT]  (value not drawn)  (no BOM)
TP10  TESTPOINT  [TP_25MIL-SMT]  (value not drawn)  (no BOM)
TP11  TESTPOINT  [TP_25MIL-SMT]  (value not drawn)  (no BOM)
TP12  TESTPOINT  [TP_25MIL-SMT]  (value not drawn)  (no BOM)
TP13  TESTPOINT  [TP_25MIL-SMT]  (value not drawn)  (no BOM)
TP14  TESTPOINT  [TP_25MIL-SMT]  (value not drawn)  (no BOM)
TP15  TESTPOINT  [TP_25MIL-SMT]  (value not drawn)  (no BOM)
TP16  TESTPOINT  [TP_25MIL-SMT]  (value not drawn)  (no BOM)
TP17  TESTPOINT  [TP_25MIL-SMT]  (value not drawn)  (no BOM)
TP33  TESTPOINT  [TP_25MIL-SMT]  (value not drawn)  (no BOM)
TP34  TESTPOINT  [TP_25MIL-SMT]  (value not drawn)  (no BOM)
U29  TPS62913RPUR  [RPU0010A-MFG]
U30  TPS74801DRCR  [DRC0010J]
U31  TPS74801DRCR  [DRC0010J]
U32  TPS62913RPUR  [RPU0010A-MFG]
U55  TLV75801PDRVR  [DRV0006A]

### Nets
GND: C157.2 C158.2 C159.2 C160.2 C161.2 C162.1 C163.2 C164.1 C165.2 C166.1 C167.1 C168.1 C169.2 C170.2 C171.2 C172.2 C173.1 C174.2 C175.1 C176.2 C177.2 C178.1 C179.1 C180.1 C253.1 C254.2 C255.1 C256.2 R148.1 R152.1 R154.1 R160.1 R161.1 R163.1 R363.1 R364.1 TP13.1 TP14.1 TP15.1 TP16.1 TP17.1 TP34.1 U29.4(PGND) U29.7(PSNS) U30.6(GND) U30.11(PAD) U31.6(GND) U31.11(PAD) U32.4(PGND) U32.7(PSNS) U55.3(GND) U55.7(PAD)
VDD_AM263P_1V2: C157.1 C158.1 C159.1 L2.2 R153.2 TP10.1 U29.3(VO)
VDD_ETH_1V1: C175.2 C176.1 R159.2 TP11.1 U31.9(OUT) U31.10(OUT)
VDD_ETH_2V5: C164.2 C165.1 R151.2 TP12.1 U30.9(OUT) U30.10(OUT)
VPP_AM263P_1V7: C255.2 C256.1 R362.2 TP33.1 U55.1(OUT)
VSYS_3V3: C169.1 C170.1 C171.1 C253.2 C254.1 L3.2 R147.2 R155.2 R162.2 R295.2 R296.2 TP9.1 U32.3(VO) U55.6(IN)
VSYS_5V0: C161.1 C162.2 C163.1 C167.2 C168.2 C172.1 C173.2 C174.1 C179.2 C180.2 R146.2 R149.1 R150.1 R156.2 R157.1 R158.1 TP8.1 U29.6(VIN) U30.1(IN) U30.2(IN) U31.1(IN) U31.2(IN) U32.6(VIN)
PG_VDD_1V2: R295.1 U29.5(PG) ; off-sheet PG_VDD_1V2
PG_VSYS_3V3: R296.1 U32.5(PG) ; off-sheet PG_VSYS_3V3
TPS62913_1_EN_SYNC: R146.1 U29.1(EN/SYNC)
TPS62913_1_FB: R153.1 R154.2 U29.9(FB)
TPS62913_1_NR_SS: C160.1 U29.8(NR/SS)
TPS62913_1_SCONF: R148.2 U29.10(S-CONF)
TPS62913_1_SW: L2.1 U29.2(SW)
TPS62913_2_EN_SYNC: R156.1 U32.1(EN/SYNC)
TPS62913_2_FB: R162.1 R163.2 U32.9(FB)
TPS62913_2_NR_SS: C177.1 U32.8(NR/SS)
TPS62913_2_SCONF: R160.2 U32.10(S-CONF)
TPS62913_2_SW: L3.1 U32.2(SW)
TPS74801_1_BIAS: R150.2 U30.4(BIAS)
TPS74801_1_EN: R149.2 U30.5(EN)
TPS74801_1_FB: R151.1 R152.2 U30.8(FB)
TPS74801_1_PG: R147.1 U30.3(PG)
TPS74801_1_SS: C166.2 U30.7(SS)
TPS74801_2_BIAS: R158.2 U31.4(BIAS)
TPS74801_2_EN: R157.2 U31.5(EN)
TPS74801_2_FB: R159.1 R161.2 U31.8(FB)
TPS74801_2_PG: R155.1 U31.3(PG)
TPS74801_2_SS: C178.2 U31.7(SS)
VPP_LDO_EN: R364.2 U55.4(EN) ; off-sheet VPP_LDO_EN
NetR362_1: R362.1 R363.2 U55.2(FB)

Not connected (* = marked no-connect by the designer): U55 5(NC)*

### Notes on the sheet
- TPS74801 Datasheet <https://www.ti.com/store/ti/en/p/product/?p=TPS74801DRCR>
- TPS62913 Datasheet <https://www.ti.com/product/TPS62913>
- AM263P Core Digital 1.2V, 3A
- Ethernet PHY 2.5V, 1.5A
- (near R146) EN/SYNC Pin:
  - Pulled to system 5.0V, will enable power-on as the rail passes through 1.01V. Soft-start operation will occur <1ms after startup.
- (near R148) S-CONF (Smart Config) Pin, 18.2kohm:
  - 2.2MHz switching frequency
  - spread-spectrum disabled
  - output discharge enabled
- NR/SS:
  470nF provides 5mS soft-start time and reasonable RC filter for noise performance with internal reference source
- EN/SYNC Pin:
  - Pulled to system 5.0V, will enable power-on as the rail passes through 1.01V. Soft-start operation will occur <1ms after startup.
- FB:
  Resistor divider to scale output voltage nominal to 0.8V reference voltage for internal comparator
- Ethernet PHY 1.1V, 1.5A
- System 3.3V, 3A
- SS Pin:
  - TBD
- AM263P VPP 1.7V, 0.5A
- 1.2V, 3.3V Power-Good

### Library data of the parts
C157 C158 C169 C170 = CMP-0008377-2: CAP, CERM, 22 uF, 10 V, +/- 20%, X7R, 0805; Manufacturer: MuRata; SizeY_mm: 1.25; Cap_Case: 0805; SizeArea_mm2: 2.5; AEC Qualified: N; AEC Category: Q200; ValueDisplayed: 22uF; TaMin_C: -55°C; SizeAreaWB_mm2: 6.75; Value1: Unknown; U/M: EA; Value: 22uF; TaMax_C: 125°C; SizeZ_mm: 1.45; SizeX_mm: 2
C159 C171 = CMP-0009221-2: CAP, CERM, 47 uF, 10 V, +/- 20%, X7R, 1210; Manufacturer: MuRata; TaMin_C: -55°C; Polarized: N; SizeAreaWB_mm2: 14.7; Value1: Unknown; U/M: EA; Value: 47uF; TaMax_C: 125°C; SizeZ_mm: 2.7; SizeX_mm: 3.2; SizeY_mm: 2.5; Cap_Case: 1210; SizeArea_mm2: 8; Cap_F: 47µF; AEC Category: Q200
C160 C177 = CMP-0007424-4: CAP, CERM, 0.47 uF, 25 V, +/- 10%, X7R, 0603; Manufacturer: MuRata; TaMin_C: -55°C; Polarized: N; SizeAreaWB_mm2: 4.68; Value1: Unknown; U/M: EA; Value: 0.47uF; TaMax_C: 125°C; SizeZ_mm: 1; SizeX_mm: 1.6; SizeY_mm: 0.8; SizeArea_mm2: 1.28; AEC Category: Q200
C161 C172 = CMP-0064936-4: CAP, CERM, 4.7 uF, 16 V,+/- 10%, X7R, 0603; Manufacturer: MuRata; TaMin_C: -55°C; Polarized: N; SizeAreaWB_mm2: 4.68; Value1: Unknown; U/M: EA; Value: 4.7uF; TaMax_C: 125°C; SizeZ_mm: 1; SizeX_mm: 1.6; SizeY_mm: 0.8; SizeArea_mm2: 1.28; AEC Category: Q200
C162 C173 = CMP-0035346-1: 1µF ±10% 10V Ceramic Capacitor X7S 0402 (1005 Metric); Manufacturer: Murata; AEC Qualified: No; SizeZ_mm: 0.6mm; TempCo: 22%
C163 C165 C174 C176 = CMP-0006659-2: CAP, CERM, 0.1 uF, 25 V, +/- 10%, X7R, 0402; Manufacturer: MuRata; TaMin_C: -55°C; Polarized: N; SizeAreaWB_mm2: 3; Value1: Unknown; U/M: EA; Value: 0.1uF; TaMax_C: 125°C; SizeZ_mm: 0.6; SizeX_mm: 1; SizeY_mm: 0.5; Cap_F: 100nF; AEC Category: Q200
C164 C167 C168 C175 C179 C180 = CMP-0087970-1: as C102 on sheet PROC171_System_Power_1
C166 C178 = CMP-0035196-1: Ceramic Capacitor for Automotive 2.7nF ±10% 100VDC X7R 0402 Paper T/R; Manufacturer: Murata; TempCo: 15%; Tolerance_%: 0.1%; SizeZ_mm: 0.55mm; AEC Qualified: Yes; AEC Grade: Grade 1
C253 C255 = CMP-0096855-1: Chip Multilayer Ceramic Capacitors for General Purpose, 0402, 0.10uF, X7R, 15%, 10%, 50V; Manufacturer: Murata; SizeZ_mm: 0.55mm; Value: 100nF; AEC Qualified: No
C254 = CMP-0043010-1: 10 µF ±20% 10V Ceramic Capacitor X5R 0402 (1005 Metric); Manufacturer: KYOCERA AVX; AEC Qualified: No; Cap_F: 10µF; SizeZ_mm: 0.7mm; TempCo: 15%; Value: 10µF
C256 = CMP-0006610-2: CAP, CERM, 2.2 uF, 25 V, +/- 10%, X5R, 0402; Manufacturer: MuRata; TaMin_C: -55°C; Polarized: N; SizeAreaWB_mm2: 3; Value1: Unknown; U/M: EA; Value: 2.2uF; TaMax_C: 85°C; SizeZ_mm: 0.7; SizeX_mm: 1; SizeY_mm: 0.5; Cap_Case: 0402; Cap_F: 2.2µF; AEC Category: Q200
L2 L3 = CMP-0064169-1: Inductor, Shielded, 2.2 uH, 4.7 A, 0.029 ohm, SMD; Manufacturer: Wurth Elektronik; Isat: 6.2A @ 20% inductance drop; Irms: 4.7A @ 40C rise; Green_Lifecycle: Active; SizeAreaWB_mm2: 26.01; DCR_ohm: 29m; Green_REACh: Passed; Value: 2.2uH; Imax_A: 4.7A; SizeZ_mm: 2.1; SizeX_mm: 4.1; SizeArea_mm2: 16.81; Ind_H: 2.2µH; AEC Qualified: N; AEC Category: Q200
R146 R147 R155 R156 R295 R296 R364 = CMP-0026658-1: as R92 on sheet PROC171_System_Power_1
R148 R160 = CMP-0021602-3: RES, 18.2 k, 1%, 0.125 W, AEC-Q200 Grade 0, 0805; Manufacturer: Panasonic; Power_W: 125mW; TempCo: 100 ppm/C; Value_Code: 18k2; Value: 18.2k; EIA_Code: E96; SizeX_mm: 2; SizeY_mm: 1.25; SizeZ_mm: 1.45; Value2: 0.125W; SizeArea_mm2: 2.5; AEC Qualified: Y; AEC Category: Q200; AEC Grade: 0; SizeAreaWB_mm2: 6.75
R149 R150 R157 R158 = CMP-0026992-3: as R89 on sheet PROC171_System_Power_1
R151 = CMP-0026336-2: RES, 3.57 k, 1%, 0.063 W, AEC-Q200 Grade 0, 0402; Manufacturer: Vishay-Dale; Power_W: 63mW; TempCo: 100 ppm/C; Value_Code: 3k57; Value: 3.57k; EIA_Code: E96; SizeX_mm: 1; SizeY_mm: 0.5; SizeZ_mm: 0.6; Value2: 0.063W; AEC Qualified: Y; VDC_V: 50V; AEC Category: Q200; AEC Grade: 0
R152 = CMP-0026093-3: RES, 1.69 k, 1%, 0.063 W, AEC-Q200 Grade 0, 0402; Manufacturer: Vishay-Dale; Power_W: 63mW; TempCo: 100 ppm/C; Value_Code: 1k69; Value: 1.69k; EIA_Code: E96; SizeX_mm: 1; SizeY_mm: 0.5; SizeZ_mm: 0.6; Value2: 0.063W; AEC Qualified: Y; VDC_V: 50V; AEC Category: Q200; AEC Grade: 0
R153 = CMP-0026237-2: RES, 2.49 k, 1%, 0.063 W, AEC-Q200 Grade 0, 0402; Manufacturer: Vishay-Dale; Power_W: 63mW; TempCo: 100 ppm/C; Value_Code: 2k49; Value: 2.49k; EIA_Code: E96; SizeX_mm: 1; SizeY_mm: 0.5; SizeZ_mm: 0.6; Value2: 0.063W; AEC Qualified: Y; VDC_V: 50V; AEC Category: Q200; AEC Grade: 0
R154 R161 R163 = CMP-0026414-2: RES, 4.99 k, 1%, 0.063 W, AEC-Q200 Grade 0, 0402; Manufacturer: Vishay-Dale; Power_W: 63mW; TempCo: 100 ppm/C; Value_Code: 4k99; Value: 4.99k; EIA_Code: E96; SizeX_mm: 1; SizeY_mm: 0.5; SizeZ_mm: 0.6; Value2: 0.063W; AEC Qualified: Y; VDC_V: 50V; AEC Category: Q200; AEC Grade: 0
R159 = CMP-0026097-2: RES, 1.87 k, 1%, 0.063 W, AEC-Q200 Grade 0, 0402; Manufacturer: Vishay-Dale; Power_W: 63mW; TempCo: 100 ppm/C; Value_Code: 1k87; Value: 1.87k; EIA_Code: E96; SizeX_mm: 1; SizeY_mm: 0.5; SizeZ_mm: 0.6; Value2: 0.063W; AEC Qualified: Y; VDC_V: 50V; AEC Category: Q200; AEC Grade: 0
R162 = CMP-0026028-3: RES, 15.4 k, 1%, 0.063 W, AEC-Q200 Grade 0, 0402; Manufacturer: Vishay-Dale; Power_W: 63mW; TempCo: 100 ppm/C; Value_Code: 15k4; Value: 15.4k; EIA_Code: E96; SizeX_mm: 1; SizeY_mm: 0.5; SizeZ_mm: 0.6; Value2: 0.063W; AEC Qualified: Y; VDC_V: 50V; AEC Category: Q200; AEC Grade: 0
R362 = CMP-0023078-5: RES, 3.16 k, 1%, 0.1 W, 0603; Manufacturer: Yageo; Power_W: 100mW; TempCo: 100 ppm/C; Value_Code: 3k16; Value: 3.16k; EIA_Code: E96; SizeX_mm: 1.6; SizeY_mm: 0.8; SizeZ_mm: 1; Value2: 0.1W; SizeArea_mm2: 1.28; AEC Qualified: N; VDC_V: 75V; AEC Category: Q200; SizeAreaWB_mm2: 4.68
R363 = CMP-0026088-3: RES, 1.50 k, 1%, 0.063 W, AEC-Q200 Grade 0, 0402; Manufacturer: Vishay-Dale; Power_W: 63mW; TempCo: 100 ppm/C; Value_Code: 1k50; Value: 1.50k; EIA_Code: E96; Res_ohm: 1.5k; SizeX_mm: 1; SizeY_mm: 0.5; SizeZ_mm: 0.6; Value2: 0.063W; AEC Qualified: Y; VDC_V: 50V; AEC Category: Q200; AEC Grade: 0
TP8-TP17 TP33 TP34 = CMP-0078143-3: TEST POINT.  No entry in BOM.
U29 U32 = CMP-0089785-1: 3V to 17V, 3A Micro Noise (20µVRMS) and Micro Ripple (200µVPP) buck converter; Manufacturer: Texas Instruments; SizeZ_mm: 1mm; TJmax_C: +150°C; Output Type: AdjustableProgrammable; Switching Frequency: 1/2.2MHz; Max Duty Cycle: 55%; Number Of Outputs: 1; Nominal Supply Current: 5mA; AEC Qualified: No; Output Voltage: 0.8-5.5V; Standoff Height: 0mm
U30 U31 = CMP-0036365-5: Single Output LDO, 1.5A, Adj. (0.8 to 3.6V), Programmable Soft-Start, DRC0010J (VSON-10); Manufacturer: Texas Instruments; SizeArea_mm2: 9; Iq(Typ)(mA): 1; Vout Adj(Max)(V): 3.6; SizeY_mm: 3; Power Good: TRUE; AEC Category: Q200; Accuracy(%): 2; Rating: Catalog; Vdo(Typ)(mV): 60; Vin(Min)(V): 0.8; CompType: IC; Vin(Max)(V): 5.5; Iout(Max)(A): 1.5; AEC Qualified: N; SizeAreaWB_mm2: 16
U55 = CMP-0084398-1: 500-mA LDO, DRV0006A (WSON-6); Manufacturer: Texas Instruments; Alternate PartNumber: TLV75801PDRVT; AEC Qualified: N; Rating: Catalog; SizeX_mm: 2; SizeAreaWB_mm2: 9; SizeArea_mm2: 4; CompType: IC; SizeZ_mm: 0.8; AEC Category: Q200

## Sheet PROC171_AM263P_1_Power.SchDoc
size 431 x 279 mm; Date: Not shown in title block; ApprovedBy: Not shown in title block; CheckedBy: Not shown in title block; Author: Not shown in title block; CompanyName: Not shown in title block; Engineer: Not shown in title block; Organization: Not shown in title block; Address1: Not shown in title block; Address2: Not shown in title block; Address3: Not shown in title block; Address4: Not shown in title block; DocumentNumber: 5; Revision: Use project parameter SCH_Rev; SheetNumber: 5; SheetTotal: 27; PageSetup: Record=PageOptions¦CenterHorizontal=True¦CenterVertical=True¦PrintScale=1.00¦XCorrection=1.00¦YCorrection=1.00¦PrintKind=0¦BorderSize=5000000¦LeftOffset=0¦BottomOffset=0¦Orientation=2¦PaperLength=1000¦PaperWidth=1000¦Scale=100¦PaperSource=15¦PrintQuality=600¦MediaType=1¦DitherType=10¦PaperKind=Letter¦PrintScaleMode=1
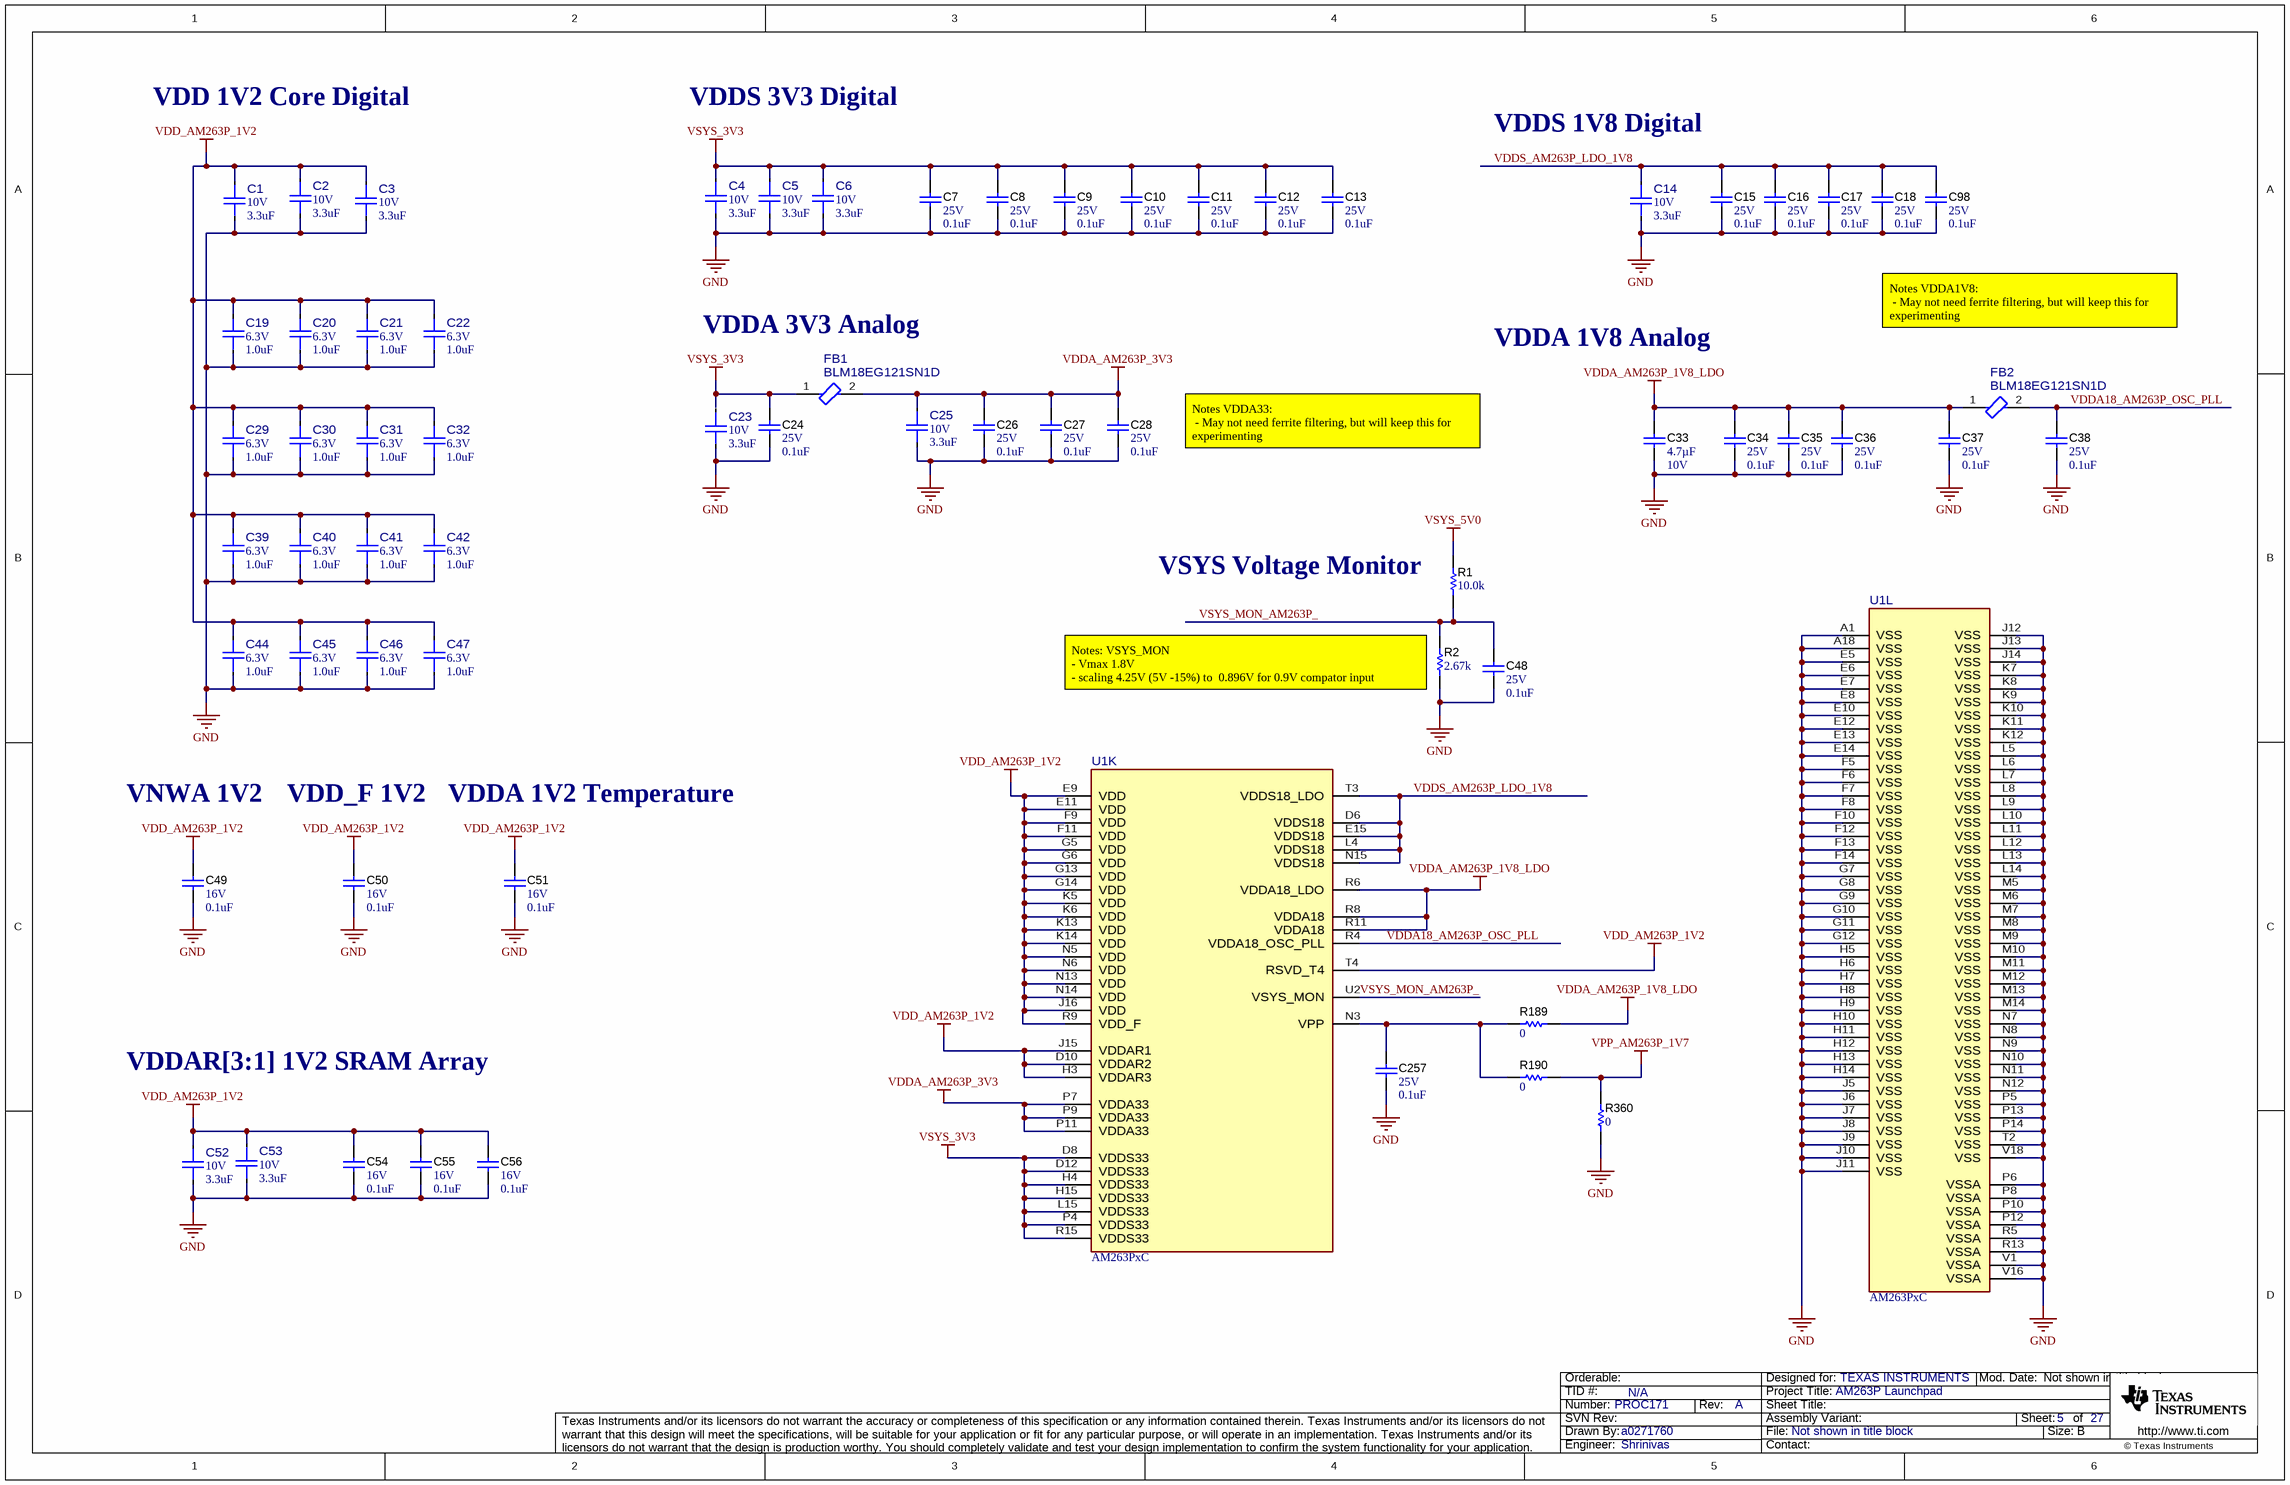
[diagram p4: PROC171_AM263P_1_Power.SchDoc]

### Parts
C1  VDC_V: 10V  ValueDisplayed: 3.3uF  [FP-CL10A335KP8NNNC_0603-MFG]  (hidden comment: CL10A335KP8NNNC)
C2  VDC_V: 10V  ValueDisplayed: 3.3uF  [FP-CL10A335KP8NNNC_0603-MFG]  (hidden comment: CL10A335KP8NNNC)
C3  VDC_V: 10V  ValueDisplayed: 3.3uF  [FP-CL10A335KP8NNNC_0603-MFG]  (hidden comment: CL10A335KP8NNNC)
C4  VDC_V: 10V  ValueDisplayed: 3.3uF  [FP-CL10A335KP8NNNC_0603-MFG]  (hidden comment: CL10A335KP8NNNC)
C5  VDC_V: 10V  ValueDisplayed: 3.3uF  [FP-CL10A335KP8NNNC_0603-MFG]  (hidden comment: CL10A335KP8NNNC)
C6  VDC_V: 10V  ValueDisplayed: 3.3uF  [FP-CL10A335KP8NNNC_0603-MFG]  (hidden comment: CL10A335KP8NNNC)
C7  VDC_V: 25V  ValueDisplayed: 0.1uF  [0402]  (hidden comment: GRM155R71E104KE14D)
C8  VDC_V: 25V  ValueDisplayed: 0.1uF  [0402]  (hidden comment: GRM155R71E104KE14D)
C9  VDC_V: 25V  ValueDisplayed: 0.1uF  [0402]  (hidden comment: GRM155R71E104KE14D)
C10  VDC_V: 25V  ValueDisplayed: 0.1uF  [0402]  (hidden comment: GRM155R71E104KE14D)
C11  VDC_V: 25V  ValueDisplayed: 0.1uF  [0402]  (hidden comment: GRM155R71E104KE14D)
C12  VDC_V: 25V  ValueDisplayed: 0.1uF  [0402]  (hidden comment: GRM155R71E104KE14D)
C13  VDC_V: 25V  ValueDisplayed: 0.1uF  [0402]  (hidden comment: GRM155R71E104KE14D)
C14  VDC_V: 10V  ValueDisplayed: 3.3uF  [FP-CL10A335KP8NNNC_0603-MFG]  (hidden comment: CL10A335KP8NNNC)
C15  VDC_V: 25V  ValueDisplayed: 0.1uF  [0402]  (hidden comment: GRM155R71E104KE14D)
C16  VDC_V: 25V  ValueDisplayed: 0.1uF  [0402]  (hidden comment: GRM155R71E104KE14D)
C17  VDC_V: 25V  ValueDisplayed: 0.1uF  [0402]  (hidden comment: GRM155R71E104KE14D)
C18  VDC_V: 25V  ValueDisplayed: 0.1uF  [0402]  (hidden comment: GRM155R71E104KE14D)
C19  VDC_V: 6.3V  ValueDisplayed: 1.0uF  [FP-GRM033C80J105ME05D_0201-MFG]  (hidden comment: GRM033C80J105ME05D)
C20  VDC_V: 6.3V  ValueDisplayed: 1.0uF  [FP-GRM033C80J105ME05D_0201-MFG]  (hidden comment: GRM033C80J105ME05D)
C21  VDC_V: 6.3V  ValueDisplayed: 1.0uF  [FP-GRM033C80J105ME05D_0201-MFG]  (hidden comment: GRM033C80J105ME05D)
C22  VDC_V: 6.3V  ValueDisplayed: 1.0uF  [FP-GRM033C80J105ME05D_0201-MFG]  (hidden comment: GRM033C80J105ME05D)
C23  VDC_V: 10V  ValueDisplayed: 3.3uF  [FP-CL10A335KP8NNNC_0603-MFG]  (hidden comment: CL10A335KP8NNNC)
C24  VDC_V: 25V  ValueDisplayed: 0.1uF  [0402]  (hidden comment: GRM155R71E104KE14D)
C25  VDC_V: 10V  ValueDisplayed: 3.3uF  [FP-CL10A335KP8NNNC_0603-MFG]  (hidden comment: CL10A335KP8NNNC)
C26  VDC_V: 25V  ValueDisplayed: 0.1uF  [0402]  (hidden comment: GRM155R71E104KE14D)
C27  VDC_V: 25V  ValueDisplayed: 0.1uF  [0402]  (hidden comment: GRM155R71E104KE14D)
C28  VDC_V: 25V  ValueDisplayed: 0.1uF  [0402]  (hidden comment: GRM155R71E104KE14D)
C29  VDC_V: 6.3V  ValueDisplayed: 1.0uF  [FP-GRM033C80J105ME05D_0201-MFG]  (hidden comment: GRM033C80J105ME05D)
C30  VDC_V: 6.3V  ValueDisplayed: 1.0uF  [FP-GRM033C80J105ME05D_0201-MFG]  (hidden comment: GRM033C80J105ME05D)
C31  VDC_V: 6.3V  ValueDisplayed: 1.0uF  [FP-GRM033C80J105ME05D_0201-MFG]  (hidden comment: GRM033C80J105ME05D)
C32  VDC_V: 6.3V  ValueDisplayed: 1.0uF  [FP-GRM033C80J105ME05D_0201-MFG]  (hidden comment: GRM033C80J105ME05D)
C33  Cap_F: 4.7µF  VDC_V: 10V  [0603]  (hidden comment: GRM188Z71A475ME15D)
C34  VDC_V: 25V  ValueDisplayed: 0.1uF  [0402]  (hidden comment: GRM155R71E104KE14D)
C35  VDC_V: 25V  ValueDisplayed: 0.1uF  [0402]  (hidden comment: GRM155R71E104KE14D)
C36  VDC_V: 25V  ValueDisplayed: 0.1uF  [0402]  (hidden comment: GRM155R71E104KE14D)
C37  VDC_V: 25V  ValueDisplayed: 0.1uF  [0402]  (hidden comment: GRM155R71E104KE14D)
C38  VDC_V: 25V  ValueDisplayed: 0.1uF  [0402]  (hidden comment: GRM155R71E104KE14D)
C39  VDC_V: 6.3V  ValueDisplayed: 1.0uF  [FP-GRM033C80J105ME05D_0201-MFG]  (hidden comment: GRM033C80J105ME05D)
C40  VDC_V: 6.3V  ValueDisplayed: 1.0uF  [FP-GRM033C80J105ME05D_0201-MFG]  (hidden comment: GRM033C80J105ME05D)
C41  VDC_V: 6.3V  ValueDisplayed: 1.0uF  [FP-GRM033C80J105ME05D_0201-MFG]  (hidden comment: GRM033C80J105ME05D)
C42  VDC_V: 6.3V  ValueDisplayed: 1.0uF  [FP-GRM033C80J105ME05D_0201-MFG]  (hidden comment: GRM033C80J105ME05D)
C44  VDC_V: 6.3V  ValueDisplayed: 1.0uF  [FP-GRM033C80J105ME05D_0201-MFG]  (hidden comment: GRM033C80J105ME05D)
C45  VDC_V: 6.3V  ValueDisplayed: 1.0uF  [FP-GRM033C80J105ME05D_0201-MFG]  (hidden comment: GRM033C80J105ME05D)
C46  VDC_V: 6.3V  ValueDisplayed: 1.0uF  [FP-GRM033C80J105ME05D_0201-MFG]  (hidden comment: GRM033C80J105ME05D)
C47  VDC_V: 6.3V  ValueDisplayed: 1.0uF  [FP-GRM033C80J105ME05D_0201-MFG]  (hidden comment: GRM033C80J105ME05D)
C48  VDC_V: 25V  ValueDisplayed: 0.1uF  [0402]  (hidden comment: GRM155R71E104KE14D)
C49  VDC_V: 16V  ValueDisplayed: 0.1uF  [0201]  (hidden comment: GRM033Z71C104KE14D)
C50  VDC_V: 16V  ValueDisplayed: 0.1uF  [0201]  (hidden comment: GRM033Z71C104KE14D)
C51  VDC_V: 16V  ValueDisplayed: 0.1uF  [0201]  (hidden comment: GRM033Z71C104KE14D)
C52  VDC_V: 10V  ValueDisplayed: 3.3uF  [FP-CL10A335KP8NNNC_0603-MFG]  (hidden comment: CL10A335KP8NNNC)
C53  VDC_V: 10V  ValueDisplayed: 3.3uF  [FP-CL10A335KP8NNNC_0603-MFG]  (hidden comment: CL10A335KP8NNNC)
C54  VDC_V: 16V  ValueDisplayed: 0.1uF  [0201]  (hidden comment: GRM033Z71C104KE14D)
C55  VDC_V: 16V  ValueDisplayed: 0.1uF  [0201]  (hidden comment: GRM033Z71C104KE14D)
C56  VDC_V: 16V  ValueDisplayed: 0.1uF  [0201]  (hidden comment: GRM033Z71C104KE14D)
C98  VDC_V: 25V  ValueDisplayed: 0.1uF  [0402]  (hidden comment: GRM155R71E104KE14D)
C257  VDC_V: 25V  ValueDisplayed: 0.1uF  [0402]  (hidden comment: GRM155R71E104KE14D)
FB1  BLM18EG121SN1D  [FP-BLM18EG121SN1D_0603-MFG]
FB2  BLM18EG121SN1D  [FP-BLM18EG121SN1D_0603-MFG]
R1  ValueDisplayed: 10.0k  [0402]  (hidden comment: ERJ-2RKF1002X)
R2  ValueDisplayed: 2.67k  [0402]  (hidden comment: CRCW04022K67FKED)
R189  value 0  [0402L]  (hidden comment: ERJ-2GE0R00X)
R190  value 0  [0402L]  (hidden comment: ERJ-2GE0R00X)
R360  value 0  [0402L]  (hidden comment: ERJ-2GE0R00X)
U1  AM263PxC  [ZCZ0324A-MFG]  (parts K,L of 13)

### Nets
GND: C1.2 C2.2 C3.2 C4.2 C5.2 C6.2 C7.2 C8.2 C9.2 C10.2 C11.2 C12.2 C13.2 C14.2 C15.2 C16.2 C17.2 C18.2 C19.1 C20.1 C21.1 C22.1 C23.2 C24.2 C25.2 C26.2 C27.2 C28.2 C29.1 C30.1 C31.1 C32.1 C33.2 C34.2 C35.2 C36.2 C37.2 C38.2 C39.1 C40.1 C41.1 C42.1 C44.1 C45.1 C46.1 C47.1 C48.2 C49.2 C50.2 C51.2 C52.2 C53.2 C54.2 C55.2 C56.2 C98.2 C257.2 R2.1 R360.1 U1.A1(VSS) U1.A18(VSS) U1.E5(VSS) U1.E6(VSS) U1.E7(VSS) U1.E8(VSS) U1.E10(VSS) U1.E12(VSS) U1.E13(VSS) U1.E14(VSS) U1.F5(VSS) U1.F6(VSS) U1.F7(VSS) U1.F8(VSS) U1.F10(VSS) U1.F12(VSS) U1.F13(VSS) U1.F14(VSS) U1.G7(VSS) U1.G8(VSS) U1.G9(VSS) U1.G10(VSS) U1.G11(VSS) U1.G12(VSS) U1.H5(VSS) U1.H6(VSS) U1.H7(VSS) U1.H8(VSS) U1.H9(VSS) U1.H10(VSS) U1.H11(VSS) U1.H12(VSS) U1.H13(VSS) U1.H14(VSS) U1.J5(VSS) U1.J6(VSS) U1.J7(VSS) U1.J8(VSS) U1.J9(VSS) U1.J10(VSS) U1.J11(VSS) U1.J12(VSS) U1.J13(VSS) U1.J14(VSS) U1.K7(VSS) U1.K8(VSS) U1.K9(VSS) U1.K10(VSS) U1.K11(VSS) U1.K12(VSS) U1.L5(VSS) U1.L6(VSS) U1.L7(VSS) U1.L8(VSS) U1.L9(VSS) U1.L10(VSS) U1.L11(VSS) U1.L12(VSS) U1.L13(VSS) U1.L14(VSS) U1.M5(VSS) U1.M6(VSS) U1.M7(VSS) U1.M8(VSS) U1.M9(VSS) U1.M10(VSS) U1.M11(VSS) U1.M12(VSS) U1.M13(VSS) U1.M14(VSS) U1.N7(VSS) U1.N8(VSS) U1.N9(VSS) U1.N10(VSS) U1.N11(VSS) U1.N12(VSS) U1.P5(VSS) U1.P6(VSSA) U1.P8(VSSA) U1.P10(VSSA) U1.P12(VSSA) U1.P13(VSS) U1.P14(VSS) U1.R5(VSSA) U1.R13(VSSA) U1.T2(VSS) U1.V1(VSSA) U1.V16(VSSA) U1.V18(VSS)
VDD_AM263P_1V2: C1.1 C2.1 C3.1 C19.2 C20.2 C21.2 C22.2 C29.2 C30.2 C31.2 C32.2 C39.2 C40.2 C41.2 C42.2 C44.2 C45.2 C46.2 C47.2 C49.1 C50.1 C51.1 C52.1 C53.1 C54.1 C55.1 C56.1 U1.D10(VDDAR2) U1.E9(VDD) U1.E11(VDD) U1.F9(VDD) U1.F11(VDD) U1.G5(VDD) U1.G6(VDD) U1.G13(VDD) U1.G14(VDD) U1.H3(VDDAR3) U1.J15(VDDAR1) U1.J16(VDD) U1.K5(VDD) U1.K6(VDD) U1.K13(VDD) U1.K14(VDD) U1.N5(VDD) U1.N6(VDD) U1.N13(VDD) U1.N14(VDD) U1.R9(VDD_F) U1.T4(RSVD_T4)
VDDA_AM263P_1V8_LDO: C33.1 C34.1 C35.1 C36.1 C37.1 FB2.1 R189.2 U1.R6(VDDA18_LDO) U1.R8(VDDA18) U1.R11(VDDA18)
VDDA_AM263P_3V3: C25.1 C26.1 C27.1 C28.1 FB1.2 U1.P7(VDDA33) U1.P9(VDDA33) U1.P11(VDDA33)
VPP_AM263P_1V7: R190.2 R360.2
VSYS_3V3: C4.1 C5.1 C6.1 C7.1 C8.1 C9.1 C10.1 C11.1 C12.1 C13.1 C24.1 FB1.1 U1.D8(VDDS33) U1.D12(VDDS33) U1.H4(VDDS33) U1.H15(VDDS33) U1.L15(VDDS33) U1.P4(VDDS33) U1.R15(VDDS33)
VSYS_5V0: R1.2
VDDA18_AM263P_OSC_PLL: C38.1 FB2.2 U1.R4(VDDA18_OSC_PLL)
VDDS_AM263P_LDO_1V8: C14.1 C15.1 C16.1 C17.1 C18.1 C98.1 U1.D6(VDDS18) U1.E15(VDDS18) U1.L4(VDDS18) U1.N15(VDDS18) U1.T3(VDDS18_LDO)
VSYS_MON_AM263P_: C48.1 R1.1 R2.2 U1.U2(VSYS_MON)
NetC257_1: C257.1 R189.1 R190.1 U1.N3(VPP)

Not connected (* = marked no-connect by the designer): C23 1

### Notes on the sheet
- VDD 1V2 Core Digital
- VDDS 3V3 Digital
- VDDS 1V8 Digital
- VDDA 3V3 Analog
- VDDA 1V8 Analog
- Notes VDDA1V8:
  - May not need ferrite filtering, but will keep this for experimenting
- Notes VDDA33:
  - May not need ferrite filtering, but will keep this for experimenting
- (near R1) VSYS Voltage Monitor
- (near R2) Notes: VSYS_MON
  - Vmax 1.8V
  - scaling 4.25V (5V -15%) to  0.896V for 0.9V compator input
- VNWA 1V2
- VDD_F 1V2
- VDDA 1V2 Temperature
- VDDAR[3:1] 1V2 SRAM Array

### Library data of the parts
C1-C6 C14 C23 C25 C52 C53 = CMP-0042976-1: Cap Ceramic 3.3uF 10V X5R ±10% Pad SMD 0603 +85°C T/R; Manufacturer: Samsung; TempCo: 15%; Value: 3.3µF; SizeZ_mm: 0.9mm; AEC Qualified: No
C7-C13 C15-C18 C24 C26-C28 C34-C38 C48 C98 C257 = CMP-0006659-2: as C163 on sheet PROC171_System_Power_2
C19-C22 C29-C32 C39-C42 C44-C47 = CMP-0093721-1: Chip Multilayer Ceramic Capacitors for General Purpose, 0201, 1.0uF, X6S, 22%, 20%, 6.3V; Manufacturer: Murata; Cap_F: 1µF; Value: 1µF; AEC Qualified: No; SizeZ_mm: 0.39mm
C33 = CMP-0007498-4: CAP, CERM, 4.7 uF, 10 V, +/- 20%, X7R, 0603; Manufacturer: MuRata; TaMin_C: -55°C; Polarized: N; SizeAreaWB_mm2: 4.68; Value1: Unknown; U/M: EA; Value: 4.7uF; TaMax_C: 125°C; SizeZ_mm: 1; SizeX_mm: 1.6; SizeY_mm: 0.8; SizeArea_mm2: 1.28; AEC Category: Q200
C49-C51 C54-C56 = CMP-0064970-1: CAP, CERM, 0.1 uF, 16 V,+/- 10%, X7R, 0201; Manufacturer: MuRata; TaMin_C: -55°C; Polarized: N; SizeAreaWB_mm2: 2.08; Value1: Unknown; U/M: EA; Value: 0.1uF; TaMax_C: 125°C; SizeZ_mm: 0.26; SizeX_mm: 0.6; SizeY_mm: 0.3; SizeArea_mm2: 0.18; Cap_F: 100nF; AEC Category: Q200
FB1 FB2 = CMP-0089199-1: 120 Ohms @ 100MHz 1  Ferrite Bead 0603 (1608 Metric) 2A 40mOhm; Manufacturer: Murata; DCR_ohm: 60m; AEC Qualified: No; Tolerance_%: 25%; SizeZ_mm: 0.95mm; Impedance At Frequency: 120Ω @ 100MHz
R1 = CMP-0026658-1: as R92 on sheet PROC171_System_Power_1
R2 = CMP-0026240-2: RES, 2.67 k, 1%, 0.063 W, AEC-Q200 Grade 0, 0402; Manufacturer: Vishay-Dale; Power_W: 63mW; TempCo: 100 ppm/C; Value_Code: 2k67; Value: 2.67k; EIA_Code: E96; SizeX_mm: 1; SizeY_mm: 0.5; SizeZ_mm: 0.6; Value2: 0.063W; AEC Qualified: Y; VDC_V: 50V; AEC Category: Q200; AEC Grade: 0
R189 R190 R360 = CMP-0026992-3: RES, 0, 5%, 0.1 W, AEC-Q200 Grade 0, 0402; Manufacturer: Panasonic; Power_W: 100mW; TempCo: 600 ppm/C; Value_Code: 0000; EIA_Code: E24; SizeX_mm: 1; SizeY_mm: 0.5; SizeZ_mm: 0.6; Value2: 0.1W; AEC Qualified: Y; VDC_V: 50V; AEC Category: Q200; SizeAreaWB_mm2: 3
U1 = CMP-0001698-2: Sitara™ Microcontroller; Manufacturer: Texas Instruments; SizeZ_mm: 1.4mm; Core Architecture: ARM Cortex-R5F; Data Bus Width: 32bits; Frequency_Fixed: 200MHz; Interface: I2C,SPI,UART,CAN,LIN,Ethernet,Other; Max Supply Voltage: 3.465V; Memory Size: 2MBytes; Memory Type: RAM; Min Supply Voltage: 1.14V; Number Of Cores: 1; Number Of I/Os: 140; Number Of I2C Channels: 4; Number Of Spi Channels: 5; Number Of Uart Channels: 6; Standoff Height: 0.35mm; AEC Category: Q200; CompType: IC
